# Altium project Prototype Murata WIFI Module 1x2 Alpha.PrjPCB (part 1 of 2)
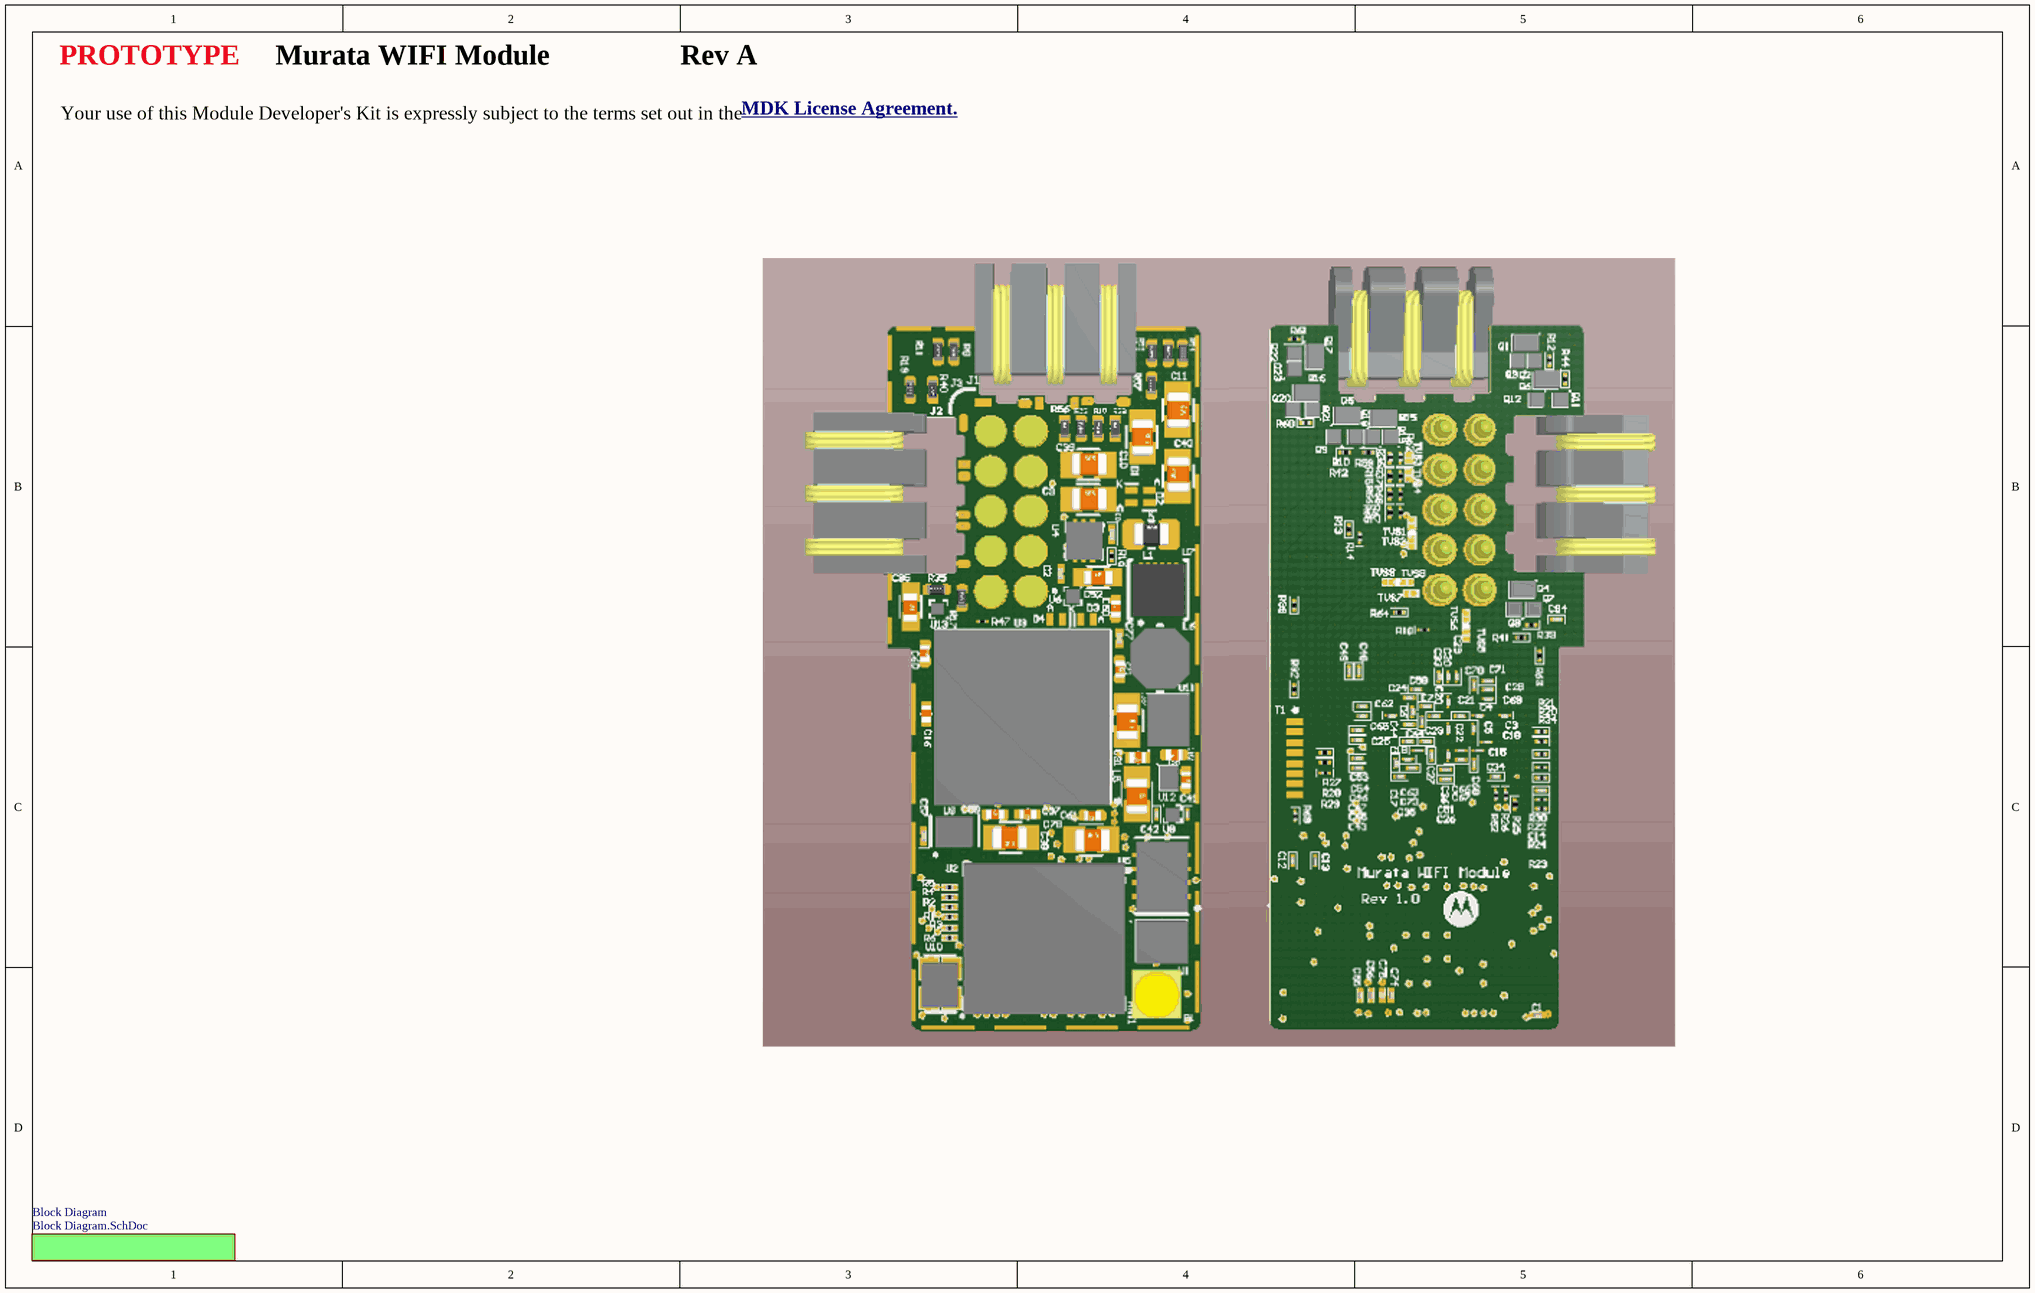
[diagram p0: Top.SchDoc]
revision: A
11 sheets, 196 parts. Net scope: flat (ports and power ports of the same name join across sheets).
Board file: Prototype Murata WIFI Module 1x2 Alpha.PcbDoc
Sheets:
  Top.SchDoc
    Block Diagram = Block Diagram.SchDoc
      EPM = EPM.SchDoc
      Host Comm = Host Comm.SchDoc
      FPGA = FPGA.SchDoc
        Banks = FPGA Banks.SchDoc
        SERDES = FPGA Serdes.SchDoc
        Power = FPGA Power.SchDoc
        Configuration = FPGA Config.SchDoc
      ARA_1X2_Power = Power.SchDoc
      WIFI Module = WIFI Module.SchDoc

## Sheet Top.SchDoc: Top (License)
size B; Date: 3/12/2014; Engineer: David McCoy (Cospan Design); DocumentNumber: 1; Revision: A; SheetNumber: 1; SheetTotal: 11

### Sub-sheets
Block Diagram = Block Diagram.SchDoc: no entries

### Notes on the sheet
- PROTOTYPE
- Murata WIFI Module
- Rev A
- Your use of this Module Developer's Kit is expressly subject to the terms set out in the
- MDK License Agreement. <http://www.projectara.com/mdk-license.txt>

## Sheet Block Diagram.SchDoc: Block Diagram
size B; Date: 10/29/2013; DrawnBy: David McCoy; Engineer: David McCoy (Cospan Design); DocumentNumber: 2; Revision: A; SheetNumber: 2; SheetTotal: 11
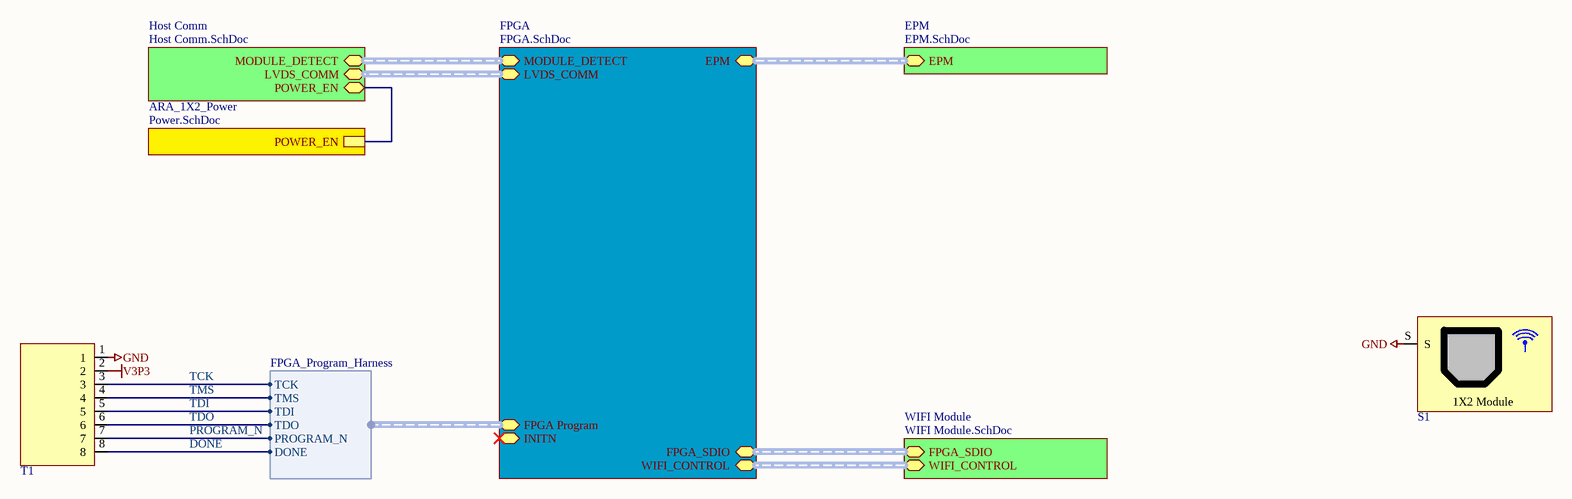
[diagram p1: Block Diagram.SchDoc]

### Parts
S1  RFSHIELD  [RFSHIELD_1X2_MODULE]  (value not drawn)  (no BOM)
T1  8 PIN TEST_INTERFACE  [8-PIN Test Interface]  (value not drawn)  (no BOM)

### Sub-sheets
ARA_1X2_Power = Power.SchDoc: POWER_EN
EPM = EPM.SchDoc: EPM (harness EPM_Harness)
FPGA = FPGA.SchDoc: EPM (harness EPM_Harness), FPGA Program (harness FPGA_Program_Harness), INITN, MODULE_DETECT (harness Module_Detect_Harness), LVDS_COMM (harness LVDS_Comm_Harness), FPGA_SDIO (harness SDIO Harness), WIFI_CONTROL (harness WIFI Control Harness)
Host Comm = Host Comm.SchDoc: MODULE_DETECT (harness Module_Detect_Harness), LVDS_COMM (harness LVDS_Comm_Harness), POWER_EN
WIFI Module = WIFI Module.SchDoc: FPGA_SDIO (harness SDIO Harness), WIFI_CONTROL (harness WIFI Control Harness)

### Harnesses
FPGA_Program_Harness: TCK, TMS, TDI, TDO, PROGRAM_N, DONE

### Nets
GND: S1.S T1.1
V3P3: T1.2
DONE: T1.8 ; sheet FPGA/FPGA Program.DONE
PROGRAM_N: T1.7 ; sheet FPGA/FPGA Program.PROGRAM_N
TCK: T1.3 ; sheet FPGA/FPGA Program.TCK
TDI: T1.5 ; sheet FPGA/FPGA Program.TDI
TDO: T1.6 ; sheet FPGA/FPGA Program.TDO
TMS: T1.4 ; sheet FPGA/FPGA Program.TMS
(unnamed): sheet Host Comm/POWER_EN, sheet ARA_1X2_Power/POWER_EN

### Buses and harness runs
harness sheet EPM/EPM = sheet FPGA/EPM
harness sheet FPGA/FPGA_SDIO = sheet WIFI Module/FPGA_SDIO
harness sheet FPGA/LVDS_COMM = sheet Host Comm/LVDS_COMM
harness sheet FPGA/MODULE_DETECT = sheet Host Comm/MODULE_DETECT
harness sheet FPGA/WIFI_CONTROL = sheet WIFI Module/WIFI_CONTROL

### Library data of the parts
S1 = S_RF_SHIELD_1X2_MODULE
T1 = TEST_INTERFACE: 8 PIN Test Interface

## Sheet EPM.SchDoc: EPM
size C; Date: 10/29/2013; DrawnBy: David McCoy; Engineer: David McCoy (Cospan Design); DocumentNumber: 10; Revision: A; SheetNumber: 10; SheetTotal: 11
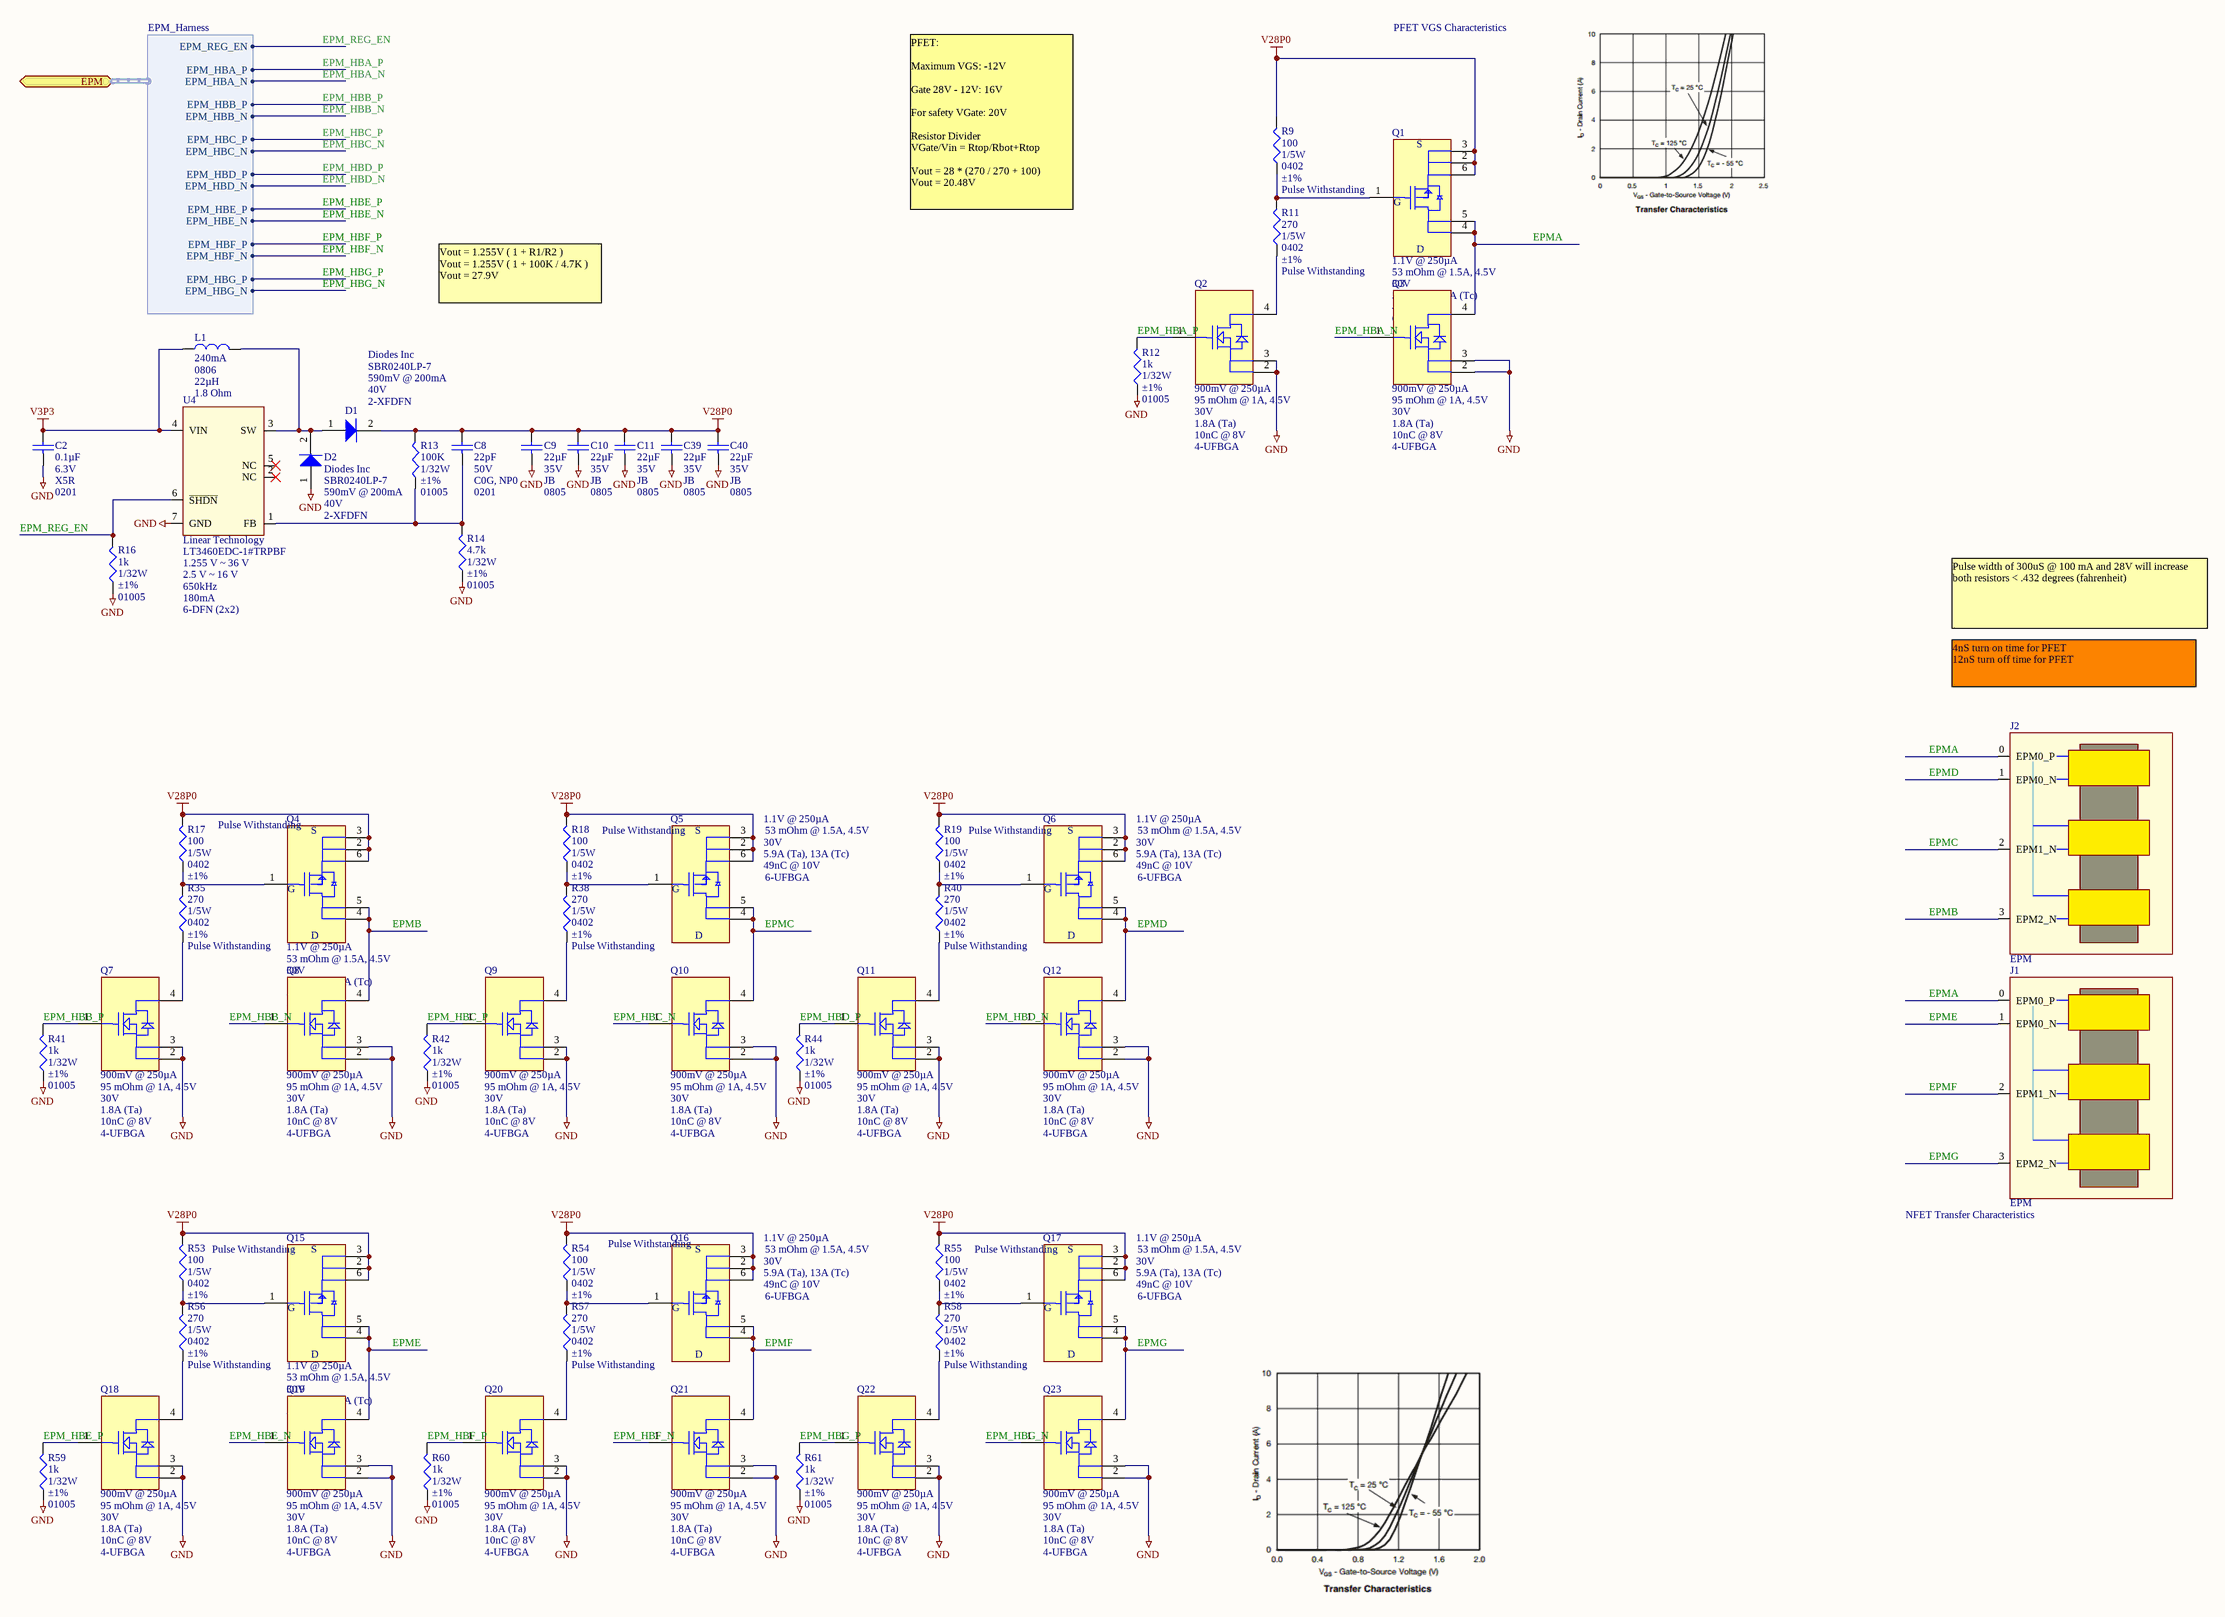
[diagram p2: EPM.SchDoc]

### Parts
C2  Capacitance: 0.1µF  Voltage - Rated: 6.3V  Temperature Coefficient: X5R  Package / Case: 0201  [CAPC0201]  (hidden comment: 0.1UF)
C8  Capacitance: 22pF  Voltage - Rated: 50V  Temperature Coefficient: C0G, NP0  Package / Case: 0201  [CAPC0201]  (hidden comment: C_0201_22pF)
C9  Voltage - Rated: 35V  Temperature Coefficient: JB  Package / Case: 0805  [C_ERA-0805]  (hidden comment: 22µF)
C10  Voltage - Rated: 35V  Temperature Coefficient: JB  Package / Case: 0805  [C_ERA-0805]  (hidden comment: 22µF)
C11  Voltage - Rated: 35V  Temperature Coefficient: JB  Package / Case: 0805  [C_ERA-0805]  (hidden comment: 22µF)
C39  Voltage - Rated: 35V  Temperature Coefficient: JB  Package / Case: 0805  [C_ERA-0805]  (hidden comment: 22µF)
C40  Voltage - Rated: 35V  Temperature Coefficient: JB  Package / Case: 0805  [C_ERA-0805]  (hidden comment: 22µF)
D1  Manufacturer: Diodes Inc  Voltage - Forward (Vf) (Max) @ If: 590mV @ 200mA  Voltage - DC Reverse (Vr) (Max): 40V  [2-XFDFN]  (hidden comment: SBR0240LP-7)
D2  Manufacturer: Diodes Inc  Voltage - Forward (Vf) (Max) @ If: 590mV @ 200mA  Voltage - DC Reverse (Vr) (Max): 40V  [2-XFDFN]  (hidden comment: SBR0240LP-7)
J1  EPM  [EPM_3X_CON_BO]  (no BOM)
J2  EPM  [EPM_3X_CON_FRANK]  (no BOM)
L1  Current: 240mA  Package / Case: 0806  Inductance: 22µH  DC Resistance (DCR): 1.8 Ohm  [L_0806]  (hidden comment: CBC2016T220K)
Q1  Vgs(th) (Max) @ Id: 1.1V @ 250µA  Rds On (Max) @ Id, Vgs: 53 mOhm @ 1.5A, 4.5V  Drain to Source Voltage (Vdss): 30V  Current - Continuous Drain (Id) @ 25° C: 5.9A (Ta), 13A (Tc)  Gate Charge (Qg) @ Vgs: 49nC @ 10V  Supplier Device Package: 6-UFBGA  [BGA6C50P3X2_145X96X59]  (hidden comment: SI8497DB-T2-E1)
Q2  Vgs(th) (Max) @ Id: 900mV @ 250µA  Rds On (Max) @ Id, Vgs: 95 mOhm @ 1A, 4.5V  Drain to Source Voltage (Vdss): 30V  Current - Continuous Drain (Id) @ 25° C: 1.8A (Ta)  Gate Charge (Qg) @ Vgs: 10nC @ 8V  Supplier Device Package: 4-UFBGA  [BGA4C40P2X2_80X80X40]  (hidden comment: SI8808DB-T2-E1)
Q3  Vgs(th) (Max) @ Id: 900mV @ 250µA  Rds On (Max) @ Id, Vgs: 95 mOhm @ 1A, 4.5V  Drain to Source Voltage (Vdss): 30V  Current - Continuous Drain (Id) @ 25° C: 1.8A (Ta)  Gate Charge (Qg) @ Vgs: 10nC @ 8V  Supplier Device Package: 4-UFBGA  [BGA4C40P2X2_80X80X40]  (hidden comment: SI8808DB-T2-E1)
Q4  Vgs(th) (Max) @ Id: 1.1V @ 250µA  Rds On (Max) @ Id, Vgs: 53 mOhm @ 1.5A, 4.5V  Drain to Source Voltage (Vdss): 30V  Current - Continuous Drain (Id) @ 25° C: 5.9A (Ta), 13A (Tc)  Gate Charge (Qg) @ Vgs: 49nC @ 10V  Supplier Device Package: 6-UFBGA  [BGA6C50P3X2_145X96X59]  (hidden comment: SI8497DB-T2-E1)
Q5  Vgs(th) (Max) @ Id: 1.1V @ 250µA  Rds On (Max) @ Id, Vgs: 53 mOhm @ 1.5A, 4.5V  Drain to Source Voltage (Vdss): 30V  Current - Continuous Drain (Id) @ 25° C: 5.9A (Ta), 13A (Tc)  Gate Charge (Qg) @ Vgs: 49nC @ 10V  Supplier Device Package: 6-UFBGA  [BGA6C50P3X2_145X96X59]  (hidden comment: SI8497DB-T2-E1)
Q6  Vgs(th) (Max) @ Id: 1.1V @ 250µA  Rds On (Max) @ Id, Vgs: 53 mOhm @ 1.5A, 4.5V  Drain to Source Voltage (Vdss): 30V  Current - Continuous Drain (Id) @ 25° C: 5.9A (Ta), 13A (Tc)  Gate Charge (Qg) @ Vgs: 49nC @ 10V  Supplier Device Package: 6-UFBGA  [BGA6C50P3X2_145X96X59]  (hidden comment: SI8497DB-T2-E1)
Q7  Vgs(th) (Max) @ Id: 900mV @ 250µA  Rds On (Max) @ Id, Vgs: 95 mOhm @ 1A, 4.5V  Drain to Source Voltage (Vdss): 30V  Current - Continuous Drain (Id) @ 25° C: 1.8A (Ta)  Gate Charge (Qg) @ Vgs: 10nC @ 8V  Supplier Device Package: 4-UFBGA  [BGA4C40P2X2_80X80X40]  (hidden comment: SI8808DB-T2-E1)
Q8  Vgs(th) (Max) @ Id: 900mV @ 250µA  Rds On (Max) @ Id, Vgs: 95 mOhm @ 1A, 4.5V  Drain to Source Voltage (Vdss): 30V  Current - Continuous Drain (Id) @ 25° C: 1.8A (Ta)  Gate Charge (Qg) @ Vgs: 10nC @ 8V  Supplier Device Package: 4-UFBGA  [BGA4C40P2X2_80X80X40]  (hidden comment: SI8808DB-T2-E1)
Q9  Vgs(th) (Max) @ Id: 900mV @ 250µA  Rds On (Max) @ Id, Vgs: 95 mOhm @ 1A, 4.5V  Drain to Source Voltage (Vdss): 30V  Current - Continuous Drain (Id) @ 25° C: 1.8A (Ta)  Gate Charge (Qg) @ Vgs: 10nC @ 8V  Supplier Device Package: 4-UFBGA  [BGA4C40P2X2_80X80X40]  (hidden comment: SI8808DB-T2-E1)
Q10  Vgs(th) (Max) @ Id: 900mV @ 250µA  Rds On (Max) @ Id, Vgs: 95 mOhm @ 1A, 4.5V  Drain to Source Voltage (Vdss): 30V  Current - Continuous Drain (Id) @ 25° C: 1.8A (Ta)  Gate Charge (Qg) @ Vgs: 10nC @ 8V  Supplier Device Package: 4-UFBGA  [BGA4C40P2X2_80X80X40]  (hidden comment: SI8808DB-T2-E1)
Q11  Vgs(th) (Max) @ Id: 900mV @ 250µA  Rds On (Max) @ Id, Vgs: 95 mOhm @ 1A, 4.5V  Drain to Source Voltage (Vdss): 30V  Current - Continuous Drain (Id) @ 25° C: 1.8A (Ta)  Gate Charge (Qg) @ Vgs: 10nC @ 8V  Supplier Device Package: 4-UFBGA  [BGA4C40P2X2_80X80X40]  (hidden comment: SI8808DB-T2-E1)
Q12  Vgs(th) (Max) @ Id: 900mV @ 250µA  Rds On (Max) @ Id, Vgs: 95 mOhm @ 1A, 4.5V  Drain to Source Voltage (Vdss): 30V  Current - Continuous Drain (Id) @ 25° C: 1.8A (Ta)  Gate Charge (Qg) @ Vgs: 10nC @ 8V  Supplier Device Package: 4-UFBGA  [BGA4C40P2X2_80X80X40]  (hidden comment: SI8808DB-T2-E1)
Q15  Vgs(th) (Max) @ Id: 1.1V @ 250µA  Rds On (Max) @ Id, Vgs: 53 mOhm @ 1.5A, 4.5V  Drain to Source Voltage (Vdss): 30V  Current - Continuous Drain (Id) @ 25° C: 5.9A (Ta), 13A (Tc)  Gate Charge (Qg) @ Vgs: 49nC @ 10V  Supplier Device Package: 6-UFBGA  [BGA6C50P3X2_145X96X59]  (hidden comment: SI8497DB-T2-E1)
Q16  Vgs(th) (Max) @ Id: 1.1V @ 250µA  Rds On (Max) @ Id, Vgs: 53 mOhm @ 1.5A, 4.5V  Drain to Source Voltage (Vdss): 30V  Current - Continuous Drain (Id) @ 25° C: 5.9A (Ta), 13A (Tc)  Gate Charge (Qg) @ Vgs: 49nC @ 10V  Supplier Device Package: 6-UFBGA  [BGA6C50P3X2_145X96X59]  (hidden comment: SI8497DB-T2-E1)
Q17  Vgs(th) (Max) @ Id: 1.1V @ 250µA  Rds On (Max) @ Id, Vgs: 53 mOhm @ 1.5A, 4.5V  Drain to Source Voltage (Vdss): 30V  Current - Continuous Drain (Id) @ 25° C: 5.9A (Ta), 13A (Tc)  Gate Charge (Qg) @ Vgs: 49nC @ 10V  Supplier Device Package: 6-UFBGA  [BGA6C50P3X2_145X96X59]  (hidden comment: SI8497DB-T2-E1)
Q18  Vgs(th) (Max) @ Id: 900mV @ 250µA  Rds On (Max) @ Id, Vgs: 95 mOhm @ 1A, 4.5V  Drain to Source Voltage (Vdss): 30V  Current - Continuous Drain (Id) @ 25° C: 1.8A (Ta)  Gate Charge (Qg) @ Vgs: 10nC @ 8V  Supplier Device Package: 4-UFBGA  [BGA4C40P2X2_80X80X40]  (hidden comment: SI8808DB-T2-E1)
Q19  Vgs(th) (Max) @ Id: 900mV @ 250µA  Rds On (Max) @ Id, Vgs: 95 mOhm @ 1A, 4.5V  Drain to Source Voltage (Vdss): 30V  Current - Continuous Drain (Id) @ 25° C: 1.8A (Ta)  Gate Charge (Qg) @ Vgs: 10nC @ 8V  Supplier Device Package: 4-UFBGA  [BGA4C40P2X2_80X80X40]  (hidden comment: SI8808DB-T2-E1)
Q20  Vgs(th) (Max) @ Id: 900mV @ 250µA  Rds On (Max) @ Id, Vgs: 95 mOhm @ 1A, 4.5V  Drain to Source Voltage (Vdss): 30V  Current - Continuous Drain (Id) @ 25° C: 1.8A (Ta)  Gate Charge (Qg) @ Vgs: 10nC @ 8V  Supplier Device Package: 4-UFBGA  [BGA4C40P2X2_80X80X40]  (hidden comment: SI8808DB-T2-E1)
Q21  Vgs(th) (Max) @ Id: 900mV @ 250µA  Rds On (Max) @ Id, Vgs: 95 mOhm @ 1A, 4.5V  Drain to Source Voltage (Vdss): 30V  Current - Continuous Drain (Id) @ 25° C: 1.8A (Ta)  Gate Charge (Qg) @ Vgs: 10nC @ 8V  Supplier Device Package: 4-UFBGA  [BGA4C40P2X2_80X80X40]  (hidden comment: SI8808DB-T2-E1)
Q22  Vgs(th) (Max) @ Id: 900mV @ 250µA  Rds On (Max) @ Id, Vgs: 95 mOhm @ 1A, 4.5V  Drain to Source Voltage (Vdss): 30V  Current - Continuous Drain (Id) @ 25° C: 1.8A (Ta)  Gate Charge (Qg) @ Vgs: 10nC @ 8V  Supplier Device Package: 4-UFBGA  [BGA4C40P2X2_80X80X40]  (hidden comment: SI8808DB-T2-E1)
Q23  Vgs(th) (Max) @ Id: 900mV @ 250µA  Rds On (Max) @ Id, Vgs: 95 mOhm @ 1A, 4.5V  Drain to Source Voltage (Vdss): 30V  Current - Continuous Drain (Id) @ 25° C: 1.8A (Ta)  Gate Charge (Qg) @ Vgs: 10nC @ 8V  Supplier Device Package: 4-UFBGA  [BGA4C40P2X2_80X80X40]  (hidden comment: SI8808DB-T2-E1)
R9  Power (Watts): 1/5W  Case: 0402  Tolerance: ±1%  [R_0402]  (hidden comment: 100)
R11  Power (Watts): 1/5W  Case: 0402  Tolerance: ±1%  [R_0402]  (hidden comment: 270)
R12  Power (Watts): 1/32W  Tolerance: ±1%  Case: 01005  [R_01005]  (hidden comment: 1k)
R13  Resistance In Ohms: 100K  Power (Watts): 1/32W  Tolerance: ±1%  Case: 01005  [R_01005]  (hidden comment: 10K)
R14  Power (Watts): 1/32W  Tolerance: ±1%  Case: 01005  [R_01005]  (hidden comment: 4.7k)
R16  Power (Watts): 1/32W  Tolerance: ±1%  Case: 01005  [R_01005]  (hidden comment: 1k)
R17  Power (Watts): 1/5W  Case: 0402  Tolerance: ±1%  [R_0402]  (hidden comment: 100)
R18  Power (Watts): 1/5W  Case: 0402  Tolerance: ±1%  [R_0402]  (hidden comment: 100)
R19  Power (Watts): 1/5W  Case: 0402  Tolerance: ±1%  [R_0402]  (hidden comment: 100)
R35  Power (Watts): 1/5W  Case: 0402  Tolerance: ±1%  [R_0402]  (hidden comment: 270)
R38  Power (Watts): 1/5W  Case: 0402  Tolerance: ±1%  [R_0402]  (hidden comment: 270)
R40  Power (Watts): 1/5W  Case: 0402  Tolerance: ±1%  [R_0402]  (hidden comment: 270)
R41  Power (Watts): 1/32W  Tolerance: ±1%  Case: 01005  [R_01005]  (hidden comment: 1k)
R42  Power (Watts): 1/32W  Tolerance: ±1%  Case: 01005  [R_01005]  (hidden comment: 1k)
R44  Power (Watts): 1/32W  Tolerance: ±1%  Case: 01005  [R_01005]  (hidden comment: 1k)
R53  Power (Watts): 1/5W  Case: 0402  Tolerance: ±1%  [R_0402]  (hidden comment: 100)
R54  Power (Watts): 1/5W  Case: 0402  Tolerance: ±1%  [R_0402]  (hidden comment: 100)
R55  Power (Watts): 1/5W  Case: 0402  Tolerance: ±1%  [R_0402]  (hidden comment: 100)
R56  Power (Watts): 1/5W  Case: 0402  Tolerance: ±1%  [R_0402]  (hidden comment: 270)
R57  Power (Watts): 1/5W  Case: 0402  Tolerance: ±1%  [R_0402]  (hidden comment: 270)
R58  Power (Watts): 1/5W  Case: 0402  Tolerance: ±1%  [R_0402]  (hidden comment: 270)
R59  Power (Watts): 1/32W  Tolerance: ±1%  Case: 01005  [R_01005]  (hidden comment: 1k)
R60  Power (Watts): 1/32W  Tolerance: ±1%  Case: 01005  [R_01005]  (hidden comment: 1k)
R61  Power (Watts): 1/32W  Tolerance: ±1%  Case: 01005  [R_01005]  (hidden comment: 1k)
U4  Manufacturer: Linear Technology  Manufacturer Part Number: LT3460EDC-1#TRPBF  Voltage - Output: 1.255 V ~ 36 V  Voltage - Input: 2.5 V ~ 16 V  Frequency - Switching: 650kHz  Current - Output: 180mA  Supplier Device Package: 6-DFN (2x2)  [DFN6]  (hidden comment: U_LT3460EDC-1)

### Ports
EPM (harness EPM_Harness)

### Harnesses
EPM_Harness: EPM_REG_EN, EPM_HBA_P, EPM_HBA_N, EPM_HBB_P, EPM_HBB_N, EPM_HBC_P, EPM_HBC_N, EPM_HBD_P, EPM_HBD_N, EPM_HBE_P, EPM_HBE_N, EPM_HBF_P, EPM_HBF_N, EPM_HBG_P, EPM_HBG_N

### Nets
GND: C2.1 C9.1 C10.1 C11.1 C39.1 C40.1 D2.1(A) Q2.2(S2) Q2.3(S) Q3.2(S2) Q3.3(S) Q7.2(S2) Q7.3(S) Q8.2(S2) Q8.3(S) Q9.2(S2) Q9.3(S) Q10.2(S2) Q10.3(S) Q11.2(S2) Q11.3(S) Q12.2(S2) Q12.3(S) Q18.2(S2) Q18.3(S) Q19.2(S2) Q19.3(S) Q20.2(S2) Q20.3(S) Q21.2(S2) Q21.3(S) Q22.2(S2) Q22.3(S) Q23.2(S2) Q23.3(S) R12.2 R14.2 R16.2 R41.2 R42.2 R44.2 R59.2 R60.2 R61.2 U4.7(GND)
V3P3: C2.2 L1.1 U4.4(VIN)
V28P0: C8.2 C9.2 C10.2 C11.2 C39.2 C40.2 D1.2(K) Q1.2(S2) Q1.3(S) Q1.6(S3) Q4.2(S2) Q4.3(S) Q4.6(S3) Q5.2(S2) Q5.3(S) Q5.6(S3) Q6.2(S2) Q6.3(S) Q6.6(S3) Q15.2(S2) Q15.3(S) Q15.6(S3) Q16.2(S2) Q16.3(S) Q16.6(S3) Q17.2(S2) Q17.3(S) Q17.6(S3) R9.1 R13.1 R17.1 R18.1 R19.1 R53.1 R54.1 R55.1
EPM_HBA_N: Q3.1(G) ; port EPM.EPM_HBA_N
EPM_HBA_P: Q2.1(G) R12.1 ; port EPM.EPM_HBA_P
EPM_HBB_N: Q8.1(G) ; port EPM.EPM_HBB_N
EPM_HBB_P: Q7.1(G) R41.1 ; port EPM.EPM_HBB_P
EPM_HBC_N: Q10.1(G) ; port EPM.EPM_HBC_N
EPM_HBC_P: Q9.1(G) R42.1 ; port EPM.EPM_HBC_P
EPM_HBD_N: Q12.1(G) ; port EPM.EPM_HBD_N
EPM_HBD_P: Q11.1(G) R44.1 ; port EPM.EPM_HBD_P
EPM_HBE_N: Q19.1(G) ; port EPM.EPM_HBE_N
EPM_HBE_P: Q18.1(G) R59.1 ; port EPM.EPM_HBE_P
EPM_HBF_N: Q21.1(G) ; port EPM.EPM_HBF_N
EPM_HBF_P: Q20.1(G) R60.1 ; port EPM.EPM_HBF_P
EPM_HBG_N: Q23.1(G) ; port EPM.EPM_HBG_N
EPM_HBG_P: Q22.1(G) R61.1 ; port EPM.EPM_HBG_P
EPM_REG_EN: R16.1 U4.6(~{SHDN}) ; port EPM.EPM_REG_EN
EPMA: J1.0(EPM0_P) J2.0(EPM0_P) Q1.4(D1) Q1.5(D2) Q3.4(D)
EPMB: J2.3(EPM2_N) Q4.4(D1) Q4.5(D2) Q8.4(D)
EPMC: J2.2(EPM1_N) Q5.4(D1) Q5.5(D2) Q10.4(D)
EPMD: J2.1(EPM0_N) Q6.4(D1) Q6.5(D2) Q12.4(D)
EPME: J1.1(EPM0_N) Q15.4(D1) Q15.5(D2) Q19.4(D)
EPMF: J1.2(EPM1_N) Q16.4(D1) Q16.5(D2) Q21.4(D)
EPMG: J1.3(EPM2_N) Q17.4(D1) Q17.5(D2) Q23.4(D)
NetC8_1: C8.1 R13.2 R14.1 U4.1(FB)
NetD1_1: D1.1(A) D2.2(K) L1.2 U4.3(SW)
NetQ1_1: Q1.1(G) R9.2 R11.1
NetQ2_4: Q2.4(D) R11.2
NetQ4_1: Q4.1(G) R17.2 R35.1
NetQ5_1: Q5.1(G) R18.2 R38.1
NetQ6_1: Q6.1(G) R19.2 R40.1
NetQ7_4: Q7.4(D) R35.2
NetQ9_4: Q9.4(D) R38.2
NetQ11_4: Q11.4(D) R40.2
NetQ15_1: Q15.1(G) R53.2 R56.1
NetQ16_1: Q16.1(G) R54.2 R57.1
NetQ17_1: Q17.1(G) R55.2 R58.1
NetQ18_4: Q18.4(D) R56.2
NetQ20_4: Q20.4(D) R57.2
NetQ22_4: Q22.4(D) R58.2

Not connected (* = marked no-connect by the designer): U4 2(NC)* 5(NC)*

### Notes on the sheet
- PFET VGS Characteristics
- PFET:
  Maximum VGS: -12V
  Gate 28V - 12V: 16V
  For safety VGate: 20V
  Resistor Divider
  VGate/Vin = Rtop/Rbot+Rtop
  Vout = 28 * (270 / 270 + 100)
  Vout = 20.48V
- Vout = 1.255V ( 1 + R1/R2 )
  Vout = 1.255V ( 1 + 100K / 4.7K )
  Vout = 27.9V
- Pulse width of 300uS @ 100 mA and 28V will increase both resistors < .432 degrees (fahrenheit)
- 4nS turn on time for PFET
  12nS turn off time for PFET
- NFET Transfer Characteristics

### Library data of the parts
C2 = C_0201_0.1UF: CAP CER 0.1UF 6.3V 10% X5R 0201; Manufacturer: TDK Corporation; Manufacturer Part Number: C0603X5R0J104M; Tolerance: ±20%
C8 = C_0201_22pF: CAP CER 22PF 50V 5% NP0 0201; Manufacturer: TDK Corporation; Manufacturer Part Number: C0603C0G1H220J030BA
C9-C11 C39 C40 = C_0805_22µF_35V: CAP CER 22UF 35V 20% JB 0805; Manufacturer: TDK Corporation; Manufacturer Part Number: C2012JB1V226M125AC
D1 D2 = D_SBR0240LP-7: DIODE SUP BARRIER 40V 0.25A 2DFN; Diode Type: Super Barrier; Current - Average Rectified (Io): 250mA; Speed: Fast Recovery =< 500ns, > 200mA (Io); Current - Reverse Leakage @ Vr: 10µA @ 40V; Thermal Resistance: 270°C/W Ja
J1 = J_EPM_3_PAD_BO
J2 = J_EPM_3_PAD_FRANK
L1 = L_0806_22uH: INDUCTOR 22UH 10% 0806 SMD; Manufacturer: Taiyo Yuden; Type: Wirewound; Current - Saturation: 250mA; Shielding: Unshielded; Frequency - Self Resonant: 16MHz; Frequency - Test: 2.52MHz
Q1 Q4-Q6 Q15-Q17 = Q_PFET_BGA_30V: MOSFET P-CH D-S 30V MICROFOOT; Manufacturer: Vishay Siliconix; FET Type: MOSFET P-Channel, Metal Oxide; FET Feature: Logic Level Gate, 2.5V Drive; Input Capacitance (Ciss) @ Vds: 1320pF @ 15V; Power - Max: 13W
Q2 Q3 Q7-Q12 Q18-Q23 = Q_NFET_BGA_30V: MOSFET N-CH D-S 30V MICROFOOT; Manufacturer: Vishay Siliconix; FET Type: MOSFET N-Channel, Metal Oxide; FET Feature: Logic Level Gate, 1.5V Drive; Input Capacitance (Ciss) @ Vds: 330pF @ 15V
R9 R17-R19 R53-R55 = R_0402_100_5%_PW: RES 100 OHM 1/5W 5% 0402 SMD; Manufacturer: Rohm Semiconductor; Manufacturer Part Number: ESR01MZPJ101; Temperature Coefficient: ±200ppm/°C
R11 R35 R38 R40 R56-R58 = R_0402_270_5%_PW: RES 270 OHM 1/5W 5% 0402 SMD; Manufacturer: Rohm Semiconductor; Manufacturer Part Number: ESR01MZPJ271; Temperature Coefficient: ±200ppm/°C
R12 R16 R41 R42 R44 R59-R61 = R_01005_1k: RES 1K OHM 1/32W 1% 01005 SM; Manufacturer: Panasonic Electronic Components; Manufacturer Part Number: ERJ-XGNF1001Y; Temperature Coefficient: ±200ppm/°C
R13 = R_01005_100K: RES 100K OHM 1/32W 1% 01005 SMD; Manufacturer: Yageo; Manufacturer Part Number: RC0100FR-07100KL; Temperature Coefficient: ±250ppm/°C
R14 = R_01005_4.7k: RES 4.7K OHM 1/32W 1% 01005 SMD; Manufacturer: Yageo; Manufacturer Part Number: RC0100FR-074K7L; Temperature Coefficient: ±250ppm/°C
U4 = U_LTC3460-1: IC REG BOOST ADJ 0.18A 6DFN; Output Type: Adjustable; Number of Outputs: 1; PWM Type: Current Mode; Synchronous Rectifier: No

## Sheet Host Comm.SchDoc: Host Comm
size B; Date: 10/29/2013; DrawnBy: David McCoy; Engineer: David McCoy (Cospan Design); DocumentNumber: 9; Revision: A; SheetNumber: 9; SheetTotal: 11
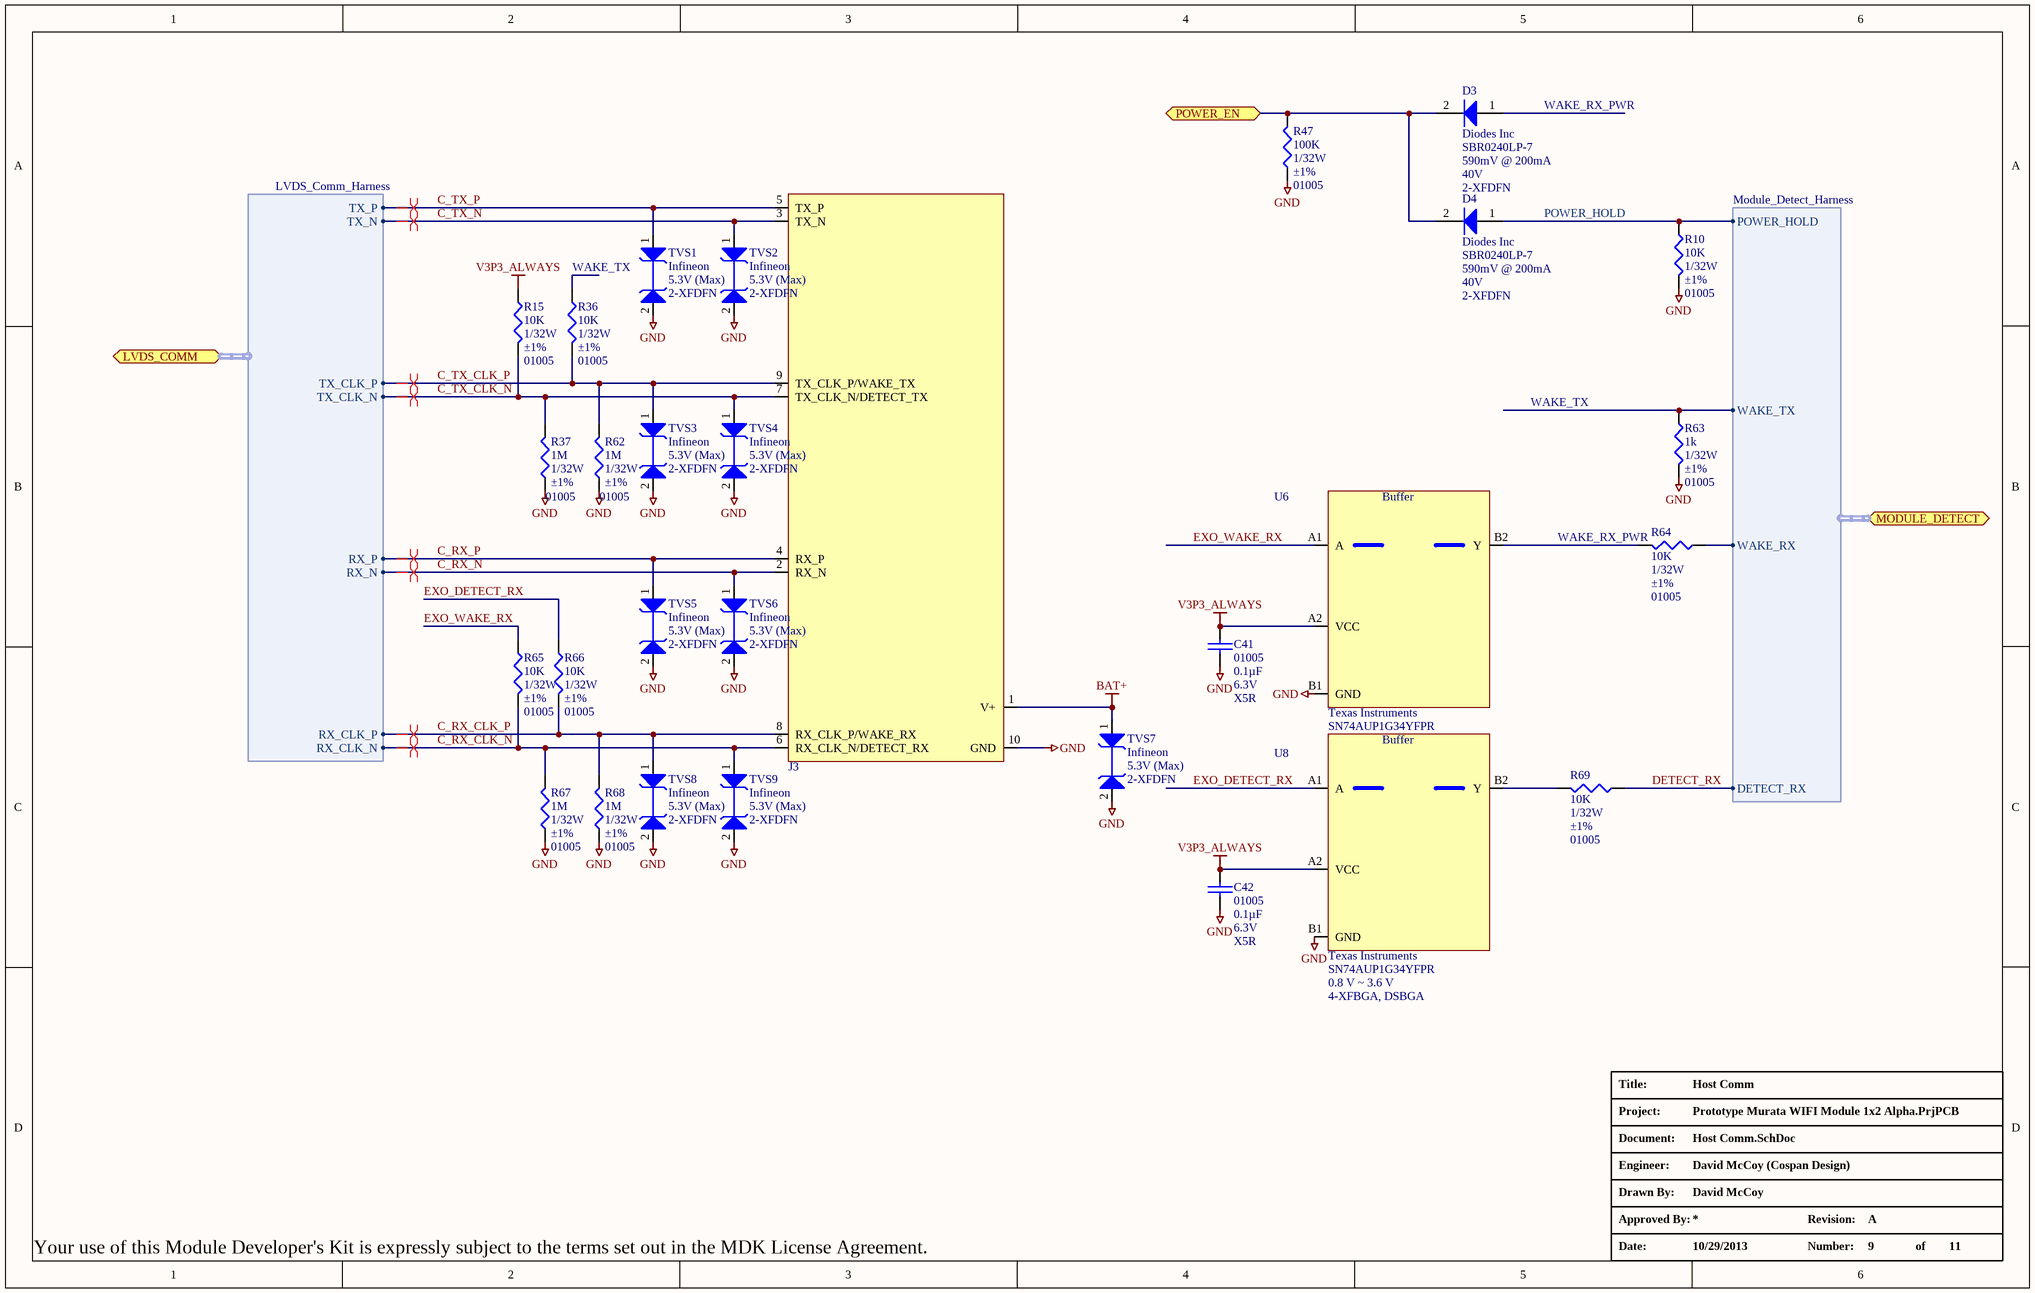
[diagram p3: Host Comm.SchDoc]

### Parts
C41  Package / Case: 01005  Capacitance: 0.1µF  Voltage - Rated: 6.3V  Temperature Coefficient: X5R  [C_01005]  (hidden comment: 0.1uF)
C42  Package / Case: 01005  Capacitance: 0.1µF  Voltage - Rated: 6.3V  Temperature Coefficient: X5R  [C_01005]  (hidden comment: 0.1uF)
D3  Manufacturer: Diodes Inc  Voltage - Forward (Vf) (Max) @ If: 590mV @ 200mA  Voltage - DC Reverse (Vr) (Max): 40V  [2-XFDFN]  (hidden comment: SBR0240LP-7)
D4  Manufacturer: Diodes Inc  Voltage - Forward (Vf) (Max) @ If: 590mV @ 200mA  Voltage - DC Reverse (Vr) (Max): 40V  [2-XFDFN]  (hidden comment: SBR0240LP-7)
J3  SPRING PIN  [10PIN SMD CONNECTOR]  (value not drawn)  (no BOM)
R10  Power (Watts): 1/32W  Tolerance: ±1%  Case: 01005  [R_01005]  (hidden comment: 10K)
R15  Power (Watts): 1/32W  Tolerance: ±1%  Case: 01005  [R_01005]  (hidden comment: 10K)
R36  Power (Watts): 1/32W  Tolerance: ±1%  Case: 01005  [R_01005]  (hidden comment: 10K)
R37  Resistance In Ohms: 1M  Power (Watts): 1/32W  Tolerance: ±1%  Case: 01005  [R_01005]  (hidden comment: 1M Ohms)
R47  Power (Watts): 1/32W  Tolerance: ±1%  Case: 01005  [R_01005]  (hidden comment: 100K)
R62  Resistance In Ohms: 1M  Power (Watts): 1/32W  Tolerance: ±1%  Case: 01005  [R_01005]  (hidden comment: 1M Ohms)
R63  Power (Watts): 1/32W  Tolerance: ±1%  Case: 01005  [R_01005]  (hidden comment: 1k)
R64  Power (Watts): 1/32W  Tolerance: ±1%  Case: 01005  [R_01005]  (hidden comment: 10K)
R65  Power (Watts): 1/32W  Tolerance: ±1%  Case: 01005  [R_01005]  (hidden comment: 10K)
R66  Power (Watts): 1/32W  Tolerance: ±1%  Case: 01005  [R_01005]  (hidden comment: 10K)
R67  Resistance In Ohms: 1M  Power (Watts): 1/32W  Tolerance: ±1%  Case: 01005  [R_01005]  (hidden comment: 1M Ohms)
R68  Resistance In Ohms: 1M  Power (Watts): 1/32W  Tolerance: ±1%  Case: 01005  [R_01005]  (hidden comment: 1M Ohms)
R69  Power (Watts): 1/32W  Tolerance: ±1%  Case: 01005  [R_01005]  (hidden comment: 10K)
TVS1  Manufacturer: Infineon  Voltage - Reverse Standoff (Typ): 5.3V (Max)  Package / Case: 2-XFDFN  [TSSLP-2-1]  (hidden comment: TVS_HS_ESD)
TVS2  Manufacturer: Infineon  Voltage - Reverse Standoff (Typ): 5.3V (Max)  Package / Case: 2-XFDFN  [TSSLP-2-1]  (hidden comment: TVS_HS_ESD)
TVS3  Manufacturer: Infineon  Voltage - Reverse Standoff (Typ): 5.3V (Max)  Package / Case: 2-XFDFN  [TSSLP-2-1]  (hidden comment: TVS_HS_ESD)
TVS4  Manufacturer: Infineon  Voltage - Reverse Standoff (Typ): 5.3V (Max)  Package / Case: 2-XFDFN  [TSSLP-2-1]  (hidden comment: TVS_HS_ESD)
TVS5  Manufacturer: Infineon  Voltage - Reverse Standoff (Typ): 5.3V (Max)  Package / Case: 2-XFDFN  [TSSLP-2-1]  (hidden comment: TVS_HS_ESD)
TVS6  Manufacturer: Infineon  Voltage - Reverse Standoff (Typ): 5.3V (Max)  Package / Case: 2-XFDFN  [TSSLP-2-1]  (hidden comment: TVS_HS_ESD)
TVS7  Manufacturer: Infineon  Voltage - Reverse Standoff (Typ): 5.3V (Max)  Package / Case: 2-XFDFN  [TSSLP-2-1]  (hidden comment: TVS_HS_ESD)
TVS8  Manufacturer: Infineon  Voltage - Reverse Standoff (Typ): 5.3V (Max)  Package / Case: 2-XFDFN  [TSSLP-2-1]  (hidden comment: TVS_HS_ESD)
TVS9  Manufacturer: Infineon  Voltage - Reverse Standoff (Typ): 5.3V (Max)  Package / Case: 2-XFDFN  [TSSLP-2-1]  (hidden comment: TVS_HS_ESD)
U6  Manufacturer: Texas Instruments  Manufacturer Part Number: SN74AUP1G34YFPR  Voltage - Supply: 0.8 V ~ 3.6 V  Package / Case: 4-XFBGA, DSBGA  [DSBGA4_.4MM]  (hidden comment: Buffer)
U8  Manufacturer: Texas Instruments  Manufacturer Part Number: SN74AUP1G34YFPR  Voltage - Supply: 0.8 V ~ 3.6 V  Package / Case: 4-XFBGA, DSBGA  [DSBGA4_.4MM]  (hidden comment: Buffer)

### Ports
LVDS_COMM (harness LVDS_Comm_Harness), MODULE_DETECT (harness Module_Detect_Harness), POWER_EN

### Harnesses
Module_Detect_Harness: WAKE_TX, WAKE_RX, DETECT_RX, POWER_HOLD
LVDS_Comm_Harness: TX_P, TX_N, TX_CLK_P, TX_CLK_N, RX_P, RX_N, RX_CLK_P, RX_CLK_N

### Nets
BAT+: J3.1(V+) TVS7.1
GND: C41.1 C42.1 J3.10(GND) R10.1 R37.2 R47.2 R62.2 R63.1 R67.2 R68.2 TVS1.2 TVS2.2 TVS3.2 TVS4.2 TVS5.2 TVS6.2 TVS7.2 TVS8.2 TVS9.2 U6.B1(GND) U8.B1(GND)
V3P3_ALWAYS: C41.2 C42.2 R15.2 U6.A2(VCC) U8.A2(VCC)
C_RX_CLK_N: J3.6(RX_CLK_N/DETECT_RX) R65.1 R67.1 TVS9.1 ; port LVDS_COMM.RX_CLK_N
C_RX_CLK_P: J3.8(RX_CLK_P/WAKE_RX) R66.1 R68.1 TVS8.1 ; port LVDS_COMM.RX_CLK_P
C_RX_N: J3.2(RX_N) TVS6.1 ; port LVDS_COMM.RX_N
C_RX_P: J3.4(RX_P) TVS5.1 ; port LVDS_COMM.RX_P
C_TX_CLK_N: J3.7(TX_CLK_N/DETECT_TX) R15.1 R37.1 TVS4.1 ; port LVDS_COMM.TX_CLK_N
C_TX_CLK_P: J3.9(TX_CLK_P/WAKE_TX) R36.1 R62.1 TVS3.1 ; port LVDS_COMM.TX_CLK_P
C_TX_N: J3.3(TX_N) TVS2.1 ; port LVDS_COMM.TX_N
C_TX_P: J3.5(TX_P) TVS1.1 ; port LVDS_COMM.TX_P
DETECT_RX: R69.2 ; port MODULE_DETECT.DETECT_RX
EXO_DETECT_RX: R66.2 U8.A1(A)
EXO_WAKE_RX: R65.2 U6.A1(A)
POWER_EN: D3.2(K) D4.2(K) R47.1 ; port POWER_EN
POWER_HOLD: D4.1(A) R10.2 ; port MODULE_DETECT.POWER_HOLD
WAKE_RX: R64.2 ; port MODULE_DETECT.WAKE_RX
WAKE_RX_PWR: D3.1(A) R64.1 U6.B2(Y)
WAKE_TX: R36.2 R63.2 ; port MODULE_DETECT.WAKE_TX
NetR69_1: R69.1 U8.B2(Y)

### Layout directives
differential pair: C_RX_CLK_N, C_RX_CLK_P, C_RX_N, C_RX_P, C_TX_CLK_N, C_TX_CLK_P, C_TX_N, C_TX_P

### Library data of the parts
C41 C42 = C_01005_0.1uF: CAP CER 0.1UF 6.3V 20% X5R 01005; Manufacturer: TDK Corporation; Manufacturer Part Number: C0402X5R0J104M020BC
D3 D4 = D_SBR0240LP-7: as D1 on sheet EPM
J3 = J_TONKA_MODULE_CONNECTOR
R10 R15 R36 R64-R66 R69 = R_01005_10K: RES 10K OHM 1/32W 1% 01005; Manufacturer: Samsung Electro-Mechanics America, Inc; Manufacturer Part Number: RC0402F103CS; Temperature Coefficient: ±250ppm/°C
R37 R62 R67 R68 = R_01005_1M: RES 1M OHM 1/32W 1% 01005 SMD; Manufacturer: Yageo; Manufacturer Part Number: RC0100FR-071ML; Temperature Coefficient: ±250ppm/°C
R47 = R_01005_100K: as R13 on sheet EPM
R63 = R_01005_1k: as R12 on sheet EPM
TVS1-TVS9 = TVS_HS_ESD: TVS DIODE 5.3VWM 28VC TSSLP2-1; Manufacturer Part Number: ESD5V3U1U-02LS E6327; Unidirectional Channels: 1; Voltage - Breakdown (Min): 6V; Voltage - Clamping (Max) @ Ipp: 28V (Typ); Current - Peak Pulse (10/1000µs): 3A (8/20µs); Power Line Protection: No; Capacitance @ Frequency: 0.4pF @ 1MHz
U6 U8 = U_SN74AUP1G34YFPR: IC BUFFER GATE SGL 4-DSBGA; Logic Type: Buffer/Line Driver, Non-Inverting; Number of Elements: 1; Current - Output High, Low: 4mA, 4mA

## Sheet FPGA.SchDoc: FPGA
size B; Date: 10/29/2013; DrawnBy: David McCoy; Engineer: David McCoy (Cospan Design); DocumentNumber: 3; Revision: A; SheetNumber: 3; SheetTotal: 11
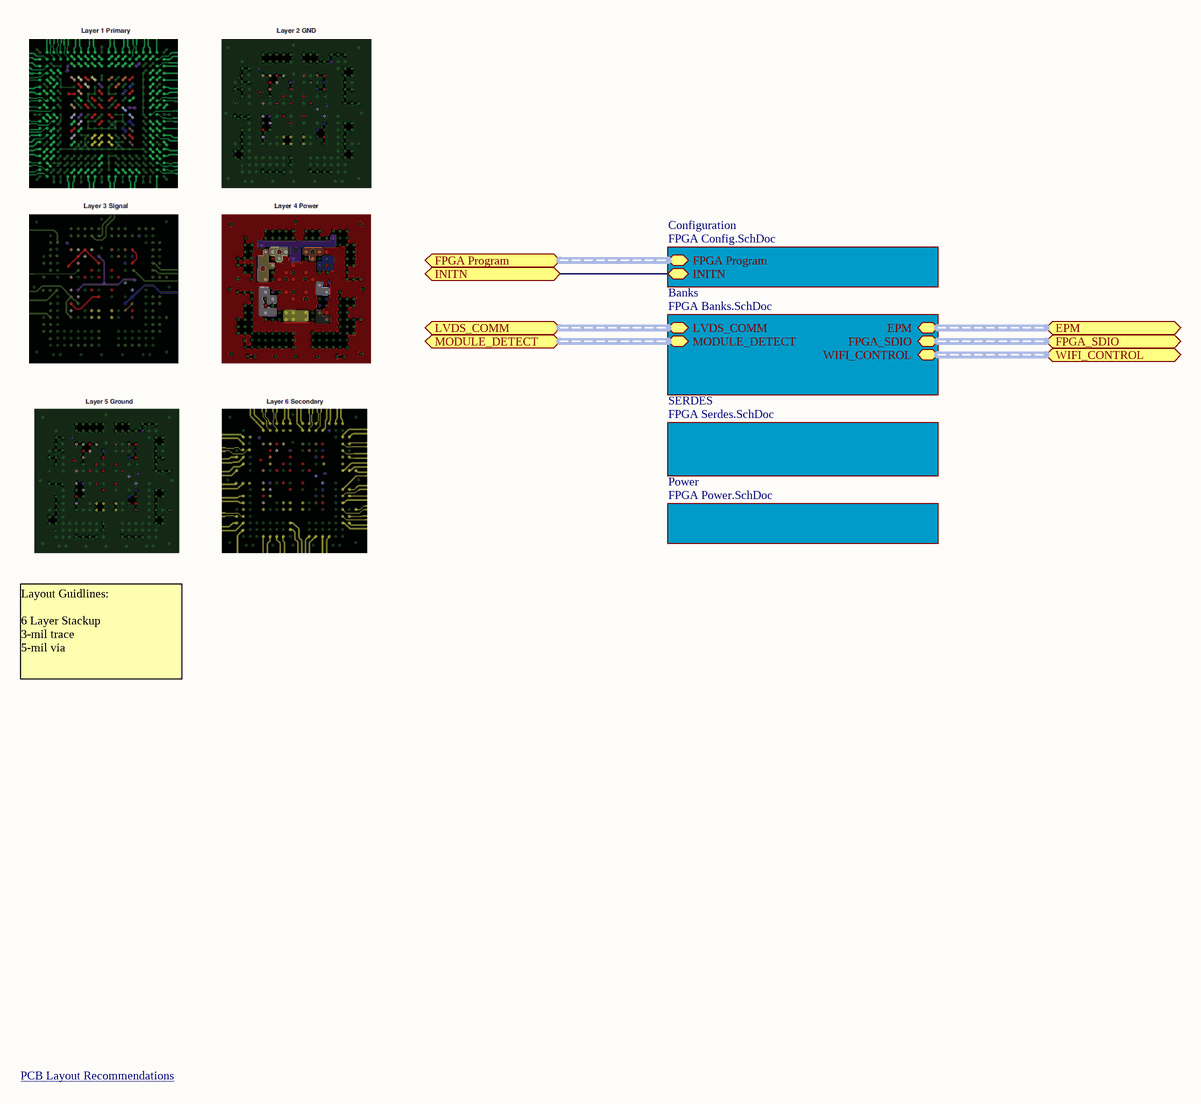
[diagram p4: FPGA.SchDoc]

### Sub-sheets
Banks = FPGA Banks.SchDoc: EPM (harness EPM_Harness), MODULE_DETECT (harness Module_Detect_Harness), LVDS_COMM (harness LVDS_Comm_Harness), FPGA_SDIO (harness SDIO Harness), WIFI_CONTROL (harness WIFI Control Harness)
Configuration = FPGA Config.SchDoc: FPGA Program (harness FPGA_Program_Harness), INITN
Power = FPGA Power.SchDoc: no entries
SERDES = FPGA Serdes.SchDoc: no entries

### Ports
EPM (harness EPM_Harness), FPGA Program (harness FPGA_Program_Harness), FPGA_SDIO (harness SDIO Harness), INITN, LVDS_COMM (harness LVDS_Comm_Harness), MODULE_DETECT (harness Module_Detect_Harness), WIFI_CONTROL (harness WIFI Control Harness)

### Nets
INITN: port INITN, sheet Configuration/INITN

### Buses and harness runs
harness port EPM = sheet Banks/EPM
harness port FPGA Program = sheet Configuration/FPGA Program
harness port FPGA_SDIO = sheet Banks/FPGA_SDIO
harness port LVDS_COMM = sheet Banks/LVDS_COMM
harness port MODULE_DETECT = sheet Banks/MODULE_DETECT
harness port WIFI_CONTROL = sheet Banks/WIFI_CONTROL

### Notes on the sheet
- Layout Guidlines:
  6 Layer Stackup
  3-mil trace
  5-mil via
- PCB Layout Recommendations <http://www.latticesemi.com/~/media/Documents/ApplicationNotes/PCBLayoutRecommendationsforBGAPackages.pdf?document_id=671>

## Sheet FPGA Banks.SchDoc: FPGA Banks
size B; Date: 10/29/2013; DrawnBy: David McCoy; Engineer: David McCoy (Cospan Design); DocumentNumber: 5; Revision: A; SheetNumber: 5; SheetTotal: 11
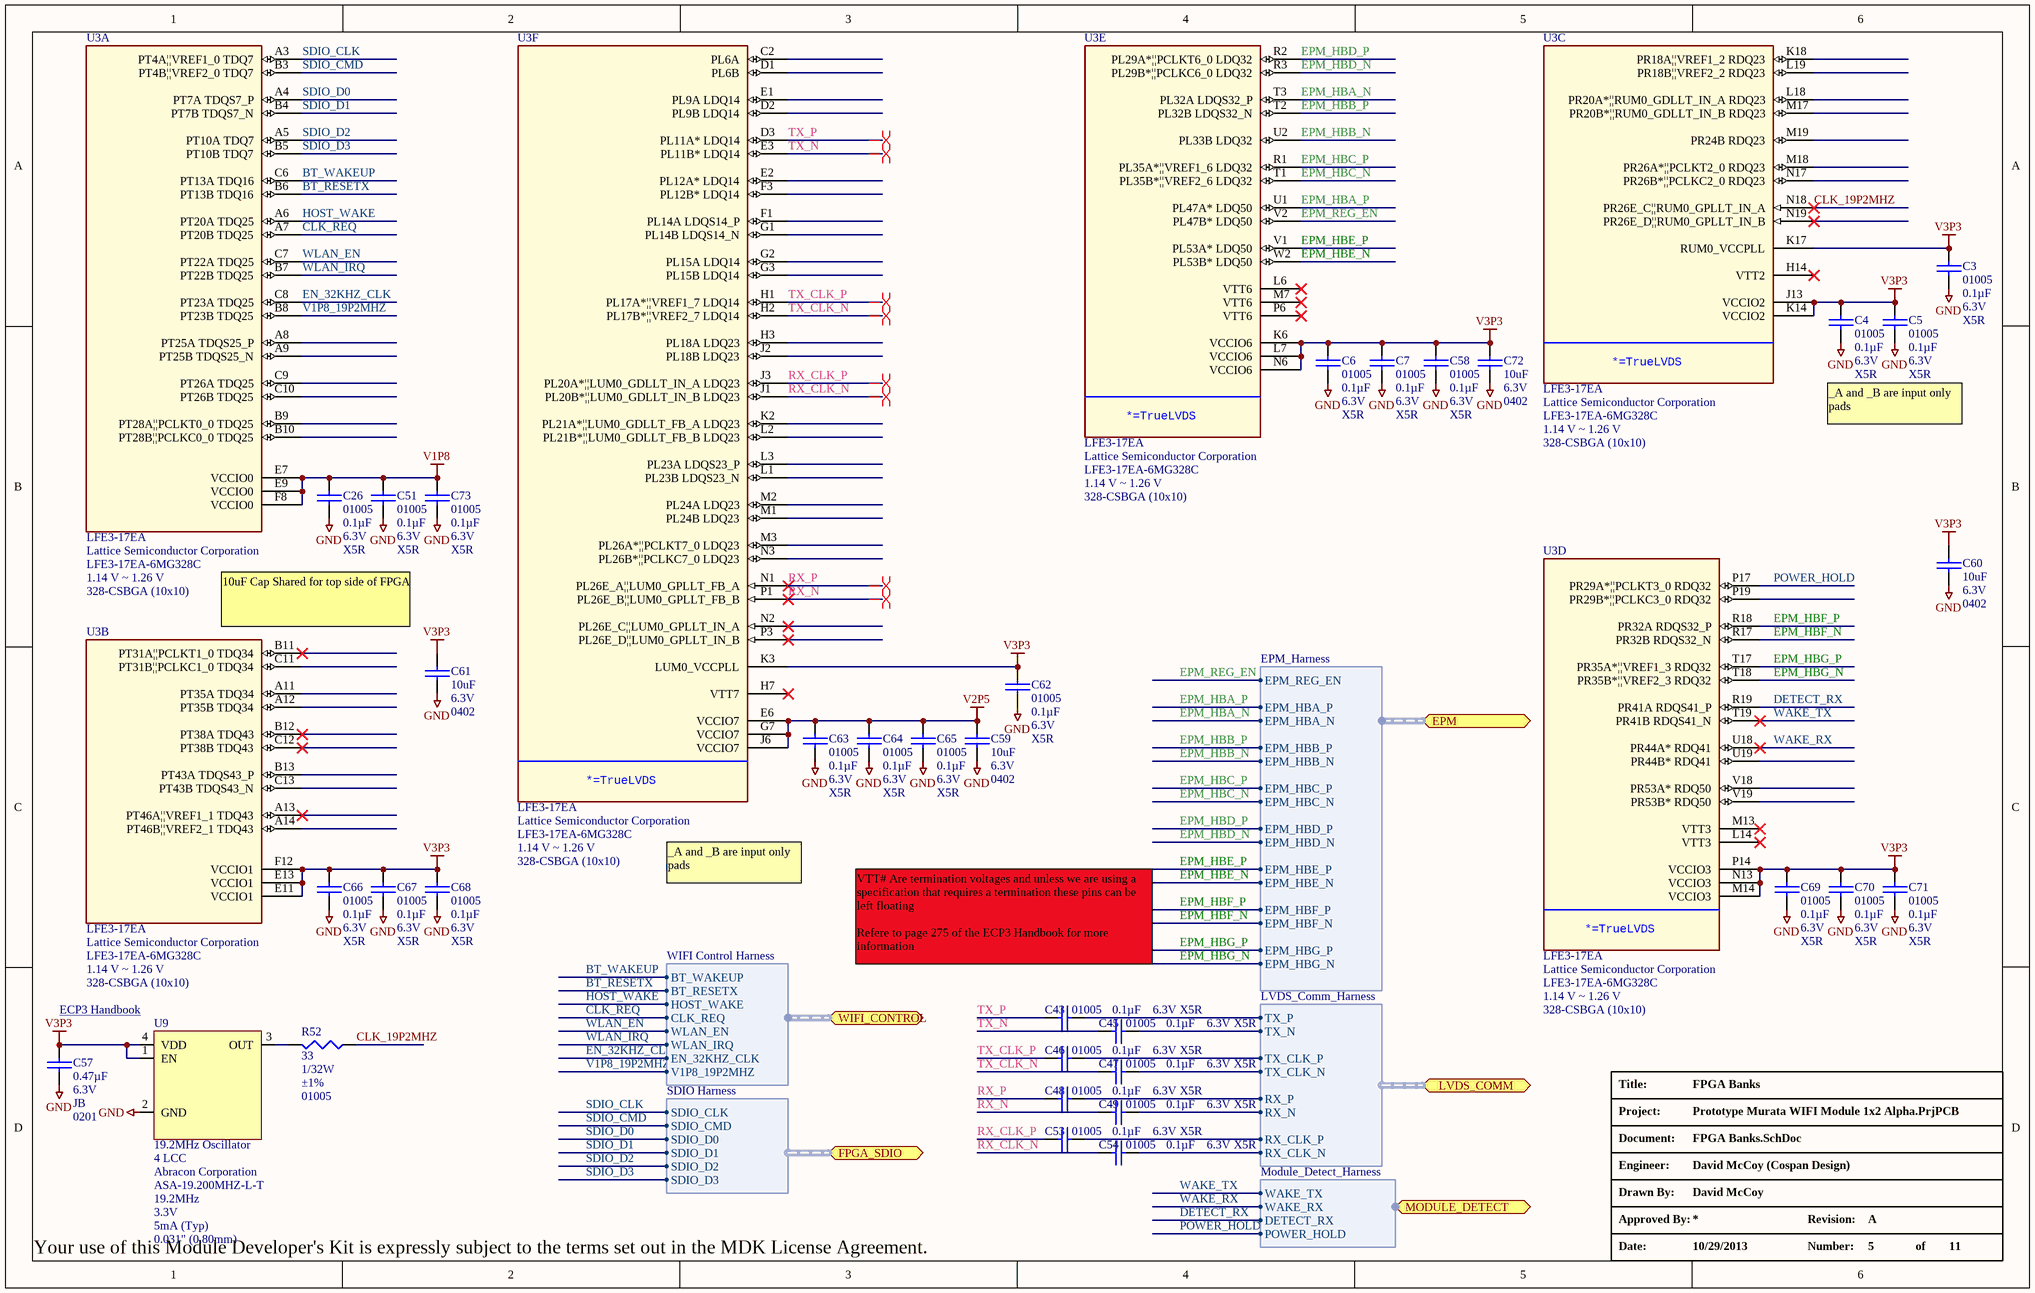
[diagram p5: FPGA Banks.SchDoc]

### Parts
C3  Package / Case: 01005  Capacitance: 0.1µF  Voltage - Rated: 6.3V  Temperature Coefficient: X5R  [C_01005]  (hidden comment: 0.1uF)
C4  Package / Case: 01005  Capacitance: 0.1µF  Voltage - Rated: 6.3V  Temperature Coefficient: X5R  [C_01005]  (hidden comment: 0.1uF)
C5  Package / Case: 01005  Capacitance: 0.1µF  Voltage - Rated: 6.3V  Temperature Coefficient: X5R  [C_01005]  (hidden comment: 0.1uF)
C6  Package / Case: 01005  Capacitance: 0.1µF  Voltage - Rated: 6.3V  Temperature Coefficient: X5R  [C_01005]  (hidden comment: 0.1uF)
C7  Package / Case: 01005  Capacitance: 0.1µF  Voltage - Rated: 6.3V  Temperature Coefficient: X5R  [C_01005]  (hidden comment: 0.1uF)
C26  Package / Case: 01005  Capacitance: 0.1µF  Voltage - Rated: 6.3V  Temperature Coefficient: X5R  [C_01005]  (hidden comment: 0.1uF)
C43  Package / Case: 01005  Capacitance: 0.1µF  Voltage - Rated: 6.3V  Temperature Coefficient: X5R  [C_01005]  (hidden comment: 0.1uF)
C45  Package / Case: 01005  Capacitance: 0.1µF  Voltage - Rated: 6.3V  Temperature Coefficient: X5R  [C_01005]  (hidden comment: 0.1uF)
C46  Package / Case: 01005  Capacitance: 0.1µF  Voltage - Rated: 6.3V  Temperature Coefficient: X5R  [C_01005]  (hidden comment: 0.1uF)
C47  Package / Case: 01005  Capacitance: 0.1µF  Voltage - Rated: 6.3V  Temperature Coefficient: X5R  [C_01005]  (hidden comment: 0.1uF)
C48  Package / Case: 01005  Capacitance: 0.1µF  Voltage - Rated: 6.3V  Temperature Coefficient: X5R  [C_01005]  (hidden comment: 0.1uF)
C49  Package / Case: 01005  Capacitance: 0.1µF  Voltage - Rated: 6.3V  Temperature Coefficient: X5R  [C_01005]  (hidden comment: 0.1uF)
C51  Package / Case: 01005  Capacitance: 0.1µF  Voltage - Rated: 6.3V  Temperature Coefficient: X5R  [C_01005]  (hidden comment: 0.1uF)
C53  Package / Case: 01005  Capacitance: 0.1µF  Voltage - Rated: 6.3V  Temperature Coefficient: X5R  [C_01005]  (hidden comment: 0.1uF)
C54  Package / Case: 01005  Capacitance: 0.1µF  Voltage - Rated: 6.3V  Temperature Coefficient: X5R  [C_01005]  (hidden comment: 0.1uF)
C57  Voltage - Rated: 6.3V  Temperature Coefficient: JB  Package / Case: 0201  [CAPC0201]  (hidden comment: 0.47µF)
C58  Package / Case: 01005  Capacitance: 0.1µF  Voltage - Rated: 6.3V  Temperature Coefficient: X5R  [C_01005]  (hidden comment: 0.1uF)
C59  Voltage - Rated: 6.3V  Package / Case: 0402  [C_0402]  (hidden comment: 10uF)
C60  Voltage - Rated: 6.3V  Package / Case: 0402  [C_0402]  (hidden comment: 10uF)
C61  Voltage - Rated: 6.3V  Package / Case: 0402  [C_0402]  (hidden comment: 10uF)
C62  Package / Case: 01005  Capacitance: 0.1µF  Voltage - Rated: 6.3V  Temperature Coefficient: X5R  [C_01005]  (hidden comment: 0.1uF)
C63  Package / Case: 01005  Capacitance: 0.1µF  Voltage - Rated: 6.3V  Temperature Coefficient: X5R  [C_01005]  (hidden comment: 0.1uF)
C64  Package / Case: 01005  Capacitance: 0.1µF  Voltage - Rated: 6.3V  Temperature Coefficient: X5R  [C_01005]  (hidden comment: 0.1uF)
C65  Package / Case: 01005  Capacitance: 0.1µF  Voltage - Rated: 6.3V  Temperature Coefficient: X5R  [C_01005]  (hidden comment: 0.1uF)
C66  Package / Case: 01005  Capacitance: 0.1µF  Voltage - Rated: 6.3V  Temperature Coefficient: X5R  [C_01005]  (hidden comment: 0.1uF)
C67  Package / Case: 01005  Capacitance: 0.1µF  Voltage - Rated: 6.3V  Temperature Coefficient: X5R  [C_01005]  (hidden comment: 0.1uF)
C68  Package / Case: 01005  Capacitance: 0.1µF  Voltage - Rated: 6.3V  Temperature Coefficient: X5R  [C_01005]  (hidden comment: 0.1uF)
C69  Package / Case: 01005  Capacitance: 0.1µF  Voltage - Rated: 6.3V  Temperature Coefficient: X5R  [C_01005]  (hidden comment: 0.1uF)
C70  Package / Case: 01005  Capacitance: 0.1µF  Voltage - Rated: 6.3V  Temperature Coefficient: X5R  [C_01005]  (hidden comment: 0.1uF)
C71  Package / Case: 01005  Capacitance: 0.1µF  Voltage - Rated: 6.3V  Temperature Coefficient: X5R  [C_01005]  (hidden comment: 0.1uF)
C72  Voltage - Rated: 6.3V  Package / Case: 0402  [C_0402]  (hidden comment: 10uF)
C73  Package / Case: 01005  Capacitance: 0.1µF  Voltage - Rated: 6.3V  Temperature Coefficient: X5R  [C_01005]  (hidden comment: 0.1uF)
R52  Power (Watts): 1/32W  Tolerance: ±1%  Case: 01005  [R_01005]  (hidden comment: 33)
U3  LFE3-17EA  Manufacturer: Lattice Semiconductor Corporation  Manufacturer Part Number: LFE3-17EA-6MG328C  Voltage - Supply: 1.14 V ~ 1.26 V  Supplier Device Package: 328-CSBGA (10x10)  [BGA328C50P19X19_1000X1000X150]  (parts A,B,C,D,E,F of 10)
U9  19.2MHz Oscillator  Package / Case: 4 LCC  Manufacturer: Abracon Corporation  Manufacturer Part Number: ASA-19.200MHZ-L-T  Frequency: 19.2MHz  Voltage - Supply: 3.3V  Current - Supply (Max): 5mA (Typ)  Height: 0.031" (0.80mm)  [LCCS165P160X200X70-4N]

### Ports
EPM (harness EPM_Harness), FPGA_SDIO (harness SDIO Harness), LVDS_COMM (harness LVDS_Comm_Harness), MODULE_DETECT (harness Module_Detect_Harness), WIFI_CONTROL (harness WIFI Control Harness)

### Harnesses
EPM_Harness: EPM_REG_EN, EPM_HBA_P, EPM_HBA_N, EPM_HBB_P, EPM_HBB_N, EPM_HBC_P, EPM_HBC_N, EPM_HBD_P, EPM_HBD_N, EPM_HBE_P, EPM_HBE_N, EPM_HBF_P, EPM_HBF_N, EPM_HBG_P, EPM_HBG_N
LVDS_Comm_Harness: TX_P, TX_N, TX_CLK_P, TX_CLK_N, RX_P, RX_N, RX_CLK_P, RX_CLK_N
Module_Detect_Harness: WAKE_TX, WAKE_RX, DETECT_RX, POWER_HOLD
SDIO Harness: SDIO_CLK, SDIO_CMD, SDIO_D0, SDIO_D1, SDIO_D2, SDIO_D3
WIFI Control Harness: BT_WAKEUP, BT_RESETX, HOST_WAKE, CLK_REQ, WLAN_EN, WLAN_IRQ, EN_32KHZ_CLK, V1P8_19P2MHZ

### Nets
GND: C3.1 C4.1 C5.1 C6.1 C7.1 C26.1 C51.1 C57.1 C58.1 C59.1 C60.1 C61.1 C62.1 C63.1 C64.1 C65.1 C66.1 C67.1 C68.1 C69.1 C70.1 C71.1 C72.1 C73.1 U9.2(GND)
V1P8: C26.2 C51.2 C73.2 U3.E7(VCCIO0) U3.E9(VCCIO0) U3.F8(VCCIO0)
V2P5: C59.2 C63.2 C64.2 C65.2 U3.E6(VCCIO7) U3.G7(VCCIO7) U3.J6(VCCIO7)
V3P3: C3.2 C4.2 C5.2 C6.2 C7.2 C57.2 C58.2 C60.2 C61.2 C62.2 C66.2 C67.2 C68.2 C69.2 C70.2 C71.2 C72.2 U3.E11(VCCIO1) U3.E13(VCCIO1) U3.F12(VCCIO1) U3.J13(VCCIO2) U3.K3(LUM0_VCCPLL) U3.K6(VCCIO6) U3.K14(VCCIO2) U3.K17(RUM0_VCCPLL) U3.L7(VCCIO6) U3.M14(VCCIO3) U3.N6(VCCIO6) U3.N13(VCCIO3) U3.P14(VCCIO3) U9.1(EN) U9.4(VDD)
BT_RESETX: U3.B6(PT13B_TDQ16) ; port WIFI_CONTROL.BT_RESETX
BT_WAKEUP: U3.C6(PT13A_TDQ16) ; port WIFI_CONTROL.BT_WAKEUP
C_RX_CLK_N: C54.1 ; port LVDS_COMM.RX_CLK_N
C_RX_CLK_P: C53.1 ; port LVDS_COMM.RX_CLK_P
C_RX_N: C49.1 ; port LVDS_COMM.RX_N
C_RX_P: C48.1 ; port LVDS_COMM.RX_P
C_TX_CLK_N: C47.1 ; port LVDS_COMM.TX_CLK_N
C_TX_CLK_P: C46.1 ; port LVDS_COMM.TX_CLK_P
C_TX_N: C45.1 ; port LVDS_COMM.TX_N
C_TX_P: C43.1 ; port LVDS_COMM.TX_P
CLK_19P2MHZ: R52.2 U3.N18(PR26E_C¦¦RUM0_GPLLT_IN_A)
CLK_REQ: U3.A7(PT20B_TDQ25) ; port WIFI_CONTROL.CLK_REQ
DETECT_RX: U3.R19(PR41A_RDQS41_P) ; port MODULE_DETECT.DETECT_RX
EN_32KHZ_CLK: U3.C8(PT23A_TDQ25) ; port WIFI_CONTROL.EN_32KHZ_CLK
EPM_HBA_N: U3.T3(PL32A_LDQS32_P) ; port EPM.EPM_HBA_N
EPM_HBA_P: U3.U1(PL47A*_LDQ50) ; port EPM.EPM_HBA_P
EPM_HBB_N: U3.U2(PL33B_LDQ32) ; port EPM.EPM_HBB_N
EPM_HBB_P: U3.T2(PL32B_LDQS32_N) ; port EPM.EPM_HBB_P
EPM_HBC_N: U3.T1(PL35B*¦¦VREF2_6_LDQ32) ; port EPM.EPM_HBC_N
EPM_HBC_P: U3.R1(PL35A*¦¦VREF1_6_LDQ32) ; port EPM.EPM_HBC_P
EPM_HBD_N: U3.R3(PL29B*¦¦PCLKC6_0_LDQ32) ; port EPM.EPM_HBD_N
EPM_HBD_P: U3.R2(PL29A*¦¦PCLKT6_0_LDQ32) ; port EPM.EPM_HBD_P
EPM_HBE_N: U3.W2(PL53B*_LDQ50) ; port EPM.EPM_HBE_N
EPM_HBE_P: U3.V1(PL53A*_LDQ50) ; port EPM.EPM_HBE_P
EPM_HBF_N: U3.R17(PR32B_RDQS32_N) ; port EPM.EPM_HBF_N
EPM_HBF_P: U3.R18(PR32A_RDQS32_P) ; port EPM.EPM_HBF_P
EPM_HBG_N: U3.T18(PR35B*¦¦VREF2_3_RDQ32) ; port EPM.EPM_HBG_N
EPM_HBG_P: U3.T17(PR35A*¦¦VREF1_3_RDQ32) ; port EPM.EPM_HBG_P
EPM_REG_EN: U3.V2(PL47B*_LDQ50) ; port EPM.EPM_REG_EN
HOST_WAKE: U3.A6(PT20A_TDQ25) ; port WIFI_CONTROL.HOST_WAKE
POWER_HOLD: U3.P17(PR29A*¦¦PCLKT3_0_RDQ32) ; port MODULE_DETECT.POWER_HOLD
RX_CLK_N: C54.2 U3.J1(PL20B*¦¦LUM0_GDLLT_IN_B_LDQ23)
RX_CLK_P: C53.2 U3.J3(PL20A*¦¦LUM0_GDLLT_IN_A_LDQ23)
RX_N: C49.2 U3.P1(PL26E_B¦¦LUM0_GPLLT_FB_B)
RX_P: C48.2 U3.N1(PL26E_A¦¦LUM0_GPLLT_FB_A)
SDIO_CLK: U3.A3(PT4A¦¦VREF1_0_TDQ7) ; port FPGA_SDIO.SDIO_CLK
SDIO_CMD: U3.B3(PT4B¦¦VREF2_0_TDQ7) ; port FPGA_SDIO.SDIO_CMD
SDIO_D0: U3.A4(PT7A_TDQS7_P) ; port FPGA_SDIO.SDIO_D0
SDIO_D1: U3.B4(PT7B_TDQS7_N) ; port FPGA_SDIO.SDIO_D1
SDIO_D2: U3.A5(PT10A_TDQ7) ; port FPGA_SDIO.SDIO_D2
SDIO_D3: U3.B5(PT10B_TDQ7) ; port FPGA_SDIO.SDIO_D3
TX_CLK_N: C47.2 U3.H2(PL17B*¦¦VREF2_7_LDQ14)
TX_CLK_P: C46.2 U3.H1(PL17A*¦¦VREF1_7_LDQ14)
TX_N: C45.2 U3.E3(PL11B*_LDQ14)
TX_P: C43.2 U3.D3(PL11A*_LDQ14)
V1P8_19P2MHZ: U3.B8(PT23B_TDQ25) ; port WIFI_CONTROL.V1P8_19P2MHZ
WAKE_RX: U3.U18(PR44A*_RDQ41) ; port MODULE_DETECT.WAKE_RX
WAKE_TX: U3.T19(PR41B_RDQS41_N) ; port MODULE_DETECT.WAKE_TX
WLAN_EN: U3.C7(PT22A_TDQ25) ; port WIFI_CONTROL.WLAN_EN
WLAN_IRQ: U3.B7(PT22B_TDQ25) ; port WIFI_CONTROL.WLAN_IRQ
NetR52_1: R52.1 U9.3(OUT)

Not connected (* = marked no-connect by the designer): U3 A8(PT25A_TDQS25_P) A9(PT25B_TDQS25_N) A11(PT35A_TDQ34) A12(PT35B_TDQ34) A13(PT46A¦¦VREF1_1_TDQ43)* A14(PT46B¦¦VREF2_1_TDQ43) B9(PT28A¦¦PCLKT0_0_TDQ25) B10(PT28B¦¦PCLKC0_0_TDQ25) B11(PT31A¦¦PCLKT1_0_TDQ34)* B12(PT38A_TDQ43)* B13(PT43A_TDQS43_P) C2(PL6A) C9(PT26A_TDQ25) C10(PT26B_TDQ25) C11(PT31B¦¦PCLKC1_0_TDQ34) C12(PT38B_TDQ43)* C13(PT43B_TDQS43_N) D1(PL6B) D2(PL9B_LDQ14) E1(PL9A_LDQ14) E2(PL12A*_LDQ14) F1(PL14A_LDQS14_P) F3(PL12B*_LDQ14) G1(PL14B_LDQS14_N) G2(PL15A_LDQ14) G3(PL15B_LDQ14) H3(PL18A_LDQ23) H7(VTT7)* H14(VTT2)* J2(PL18B_LDQ23) K2(PL21A*¦¦LUM0_GDLLT_FB_A_LDQ23) K18(PR18A¦¦VREF1_2_RDQ23) L1(PL23B_LDQS23_N) L2(PL21B*¦¦LUM0_GDLLT_FB_B_LDQ23) L3(PL23A_LDQS23_P) L6(VTT6)* L14(VTT3)* L18(PR20A*¦¦RUM0_GDLLT_IN_A_RDQ23) L19(PR18B¦¦VREF2_2_RDQ23) M1(PL24B_LDQ23) M2(PL24A_LDQ23) M3(PL26A*¦¦PCLKT7_0_LDQ23) M7(VTT6)* M13(VTT3)* M17(PR20B*¦¦RUM0_GDLLT_IN_B_RDQ23) M18(PR26A*¦¦PCLKT2_0_RDQ23) M19(PR24B_RDQ23) N2(PL26E_C¦¦LUM0_GPLLT_IN_A)* N3(PL26B*¦¦PCLKC7_0_LDQ23) N17(PR26B*¦¦PCLKC2_0_RDQ23) N19(PR26E_D¦¦RUM0_GPLLT_IN_B)* P3(PL26E_D¦¦LUM0_GPLLT_IN_B)* P6(VTT6)* P19(PR29B*¦¦PCLKC3_0_RDQ32) U19(PR44B*_RDQ41) V18(PR53A*_RDQ50) V19(PR53B*_RDQ50)

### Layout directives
differential pair: RX_CLK_N, RX_CLK_P, RX_N, RX_P, TX_CLK_N, TX_CLK_P, TX_N, TX_P

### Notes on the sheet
- _A and _B are input only pads
- (near U3) 10uF Cap Shared for top side of FPGA
- VTT# Are termination voltages and unless we are using a specification that requires a termination these pins can be left floating
  Refere to page 275 of the ECP3 Handbook for more information
- ECP3 Handbook <http://d12lxohwf1zsq3.cloudfront.net/documents/HB1009.pdf>

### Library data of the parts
C3-C7 C26 C43 C45-C49 C51 C53 C54 C58 C62-C71 C73 = C_01005_0.1uF: as C41 on sheet Host Comm
C57 = C_0201_0.47µF: CAP CER 0.47UF 6.3V 20% JB 0201; Manufacturer: TDK Corporation; Manufacturer Part Number: C0603JB0J474M030BC
C59-C61 C72 = C_0402_10uF: CAP CER 10UF 4V 20% X5R 0402; Manufacturer: Taiyo Yuden; Manufacturer Part Number: AMK105CBJ106MV-F
R52 = R_01005_33: RES 33 OHM 1/32W 1% 01005; Manufacturer: Samsung Electro-Mechanics America, Inc; Manufacturer Part Number: RC0402F330CS; Temperature Coefficient: ±300ppm/°C
U3 = U_LFE3-17EA-MG328: IC FPGA 17KLUTS 116I/O 328-BGA; SPLIT_INST: TRUE; SWAP_INFO: (S1+S2+S3+S4+S5+S6+S7+S8+S9+S10); Number of LABs/CLBs: 2125; Number of Logic Elements/Cells: 17000; Total RAM Bits: 716800; Number of I /O: 116
U9 = U_ASA-19.200MHZ-L-T: OSC 19.200 MHZ 3.3V SMD; Function: Tri-State (Output Enable); Output: HCMOS, TTL; Frequency Stability: ±50ppm

## Sheet FPGA Serdes.SchDoc: FPGA SERDES
size B; Date: 10/29/2013; DrawnBy: David McCoy; Engineer: David McCoy (Cospan Design); DocumentNumber: 6; Revision: A; SheetNumber: 6; SheetTotal: 11
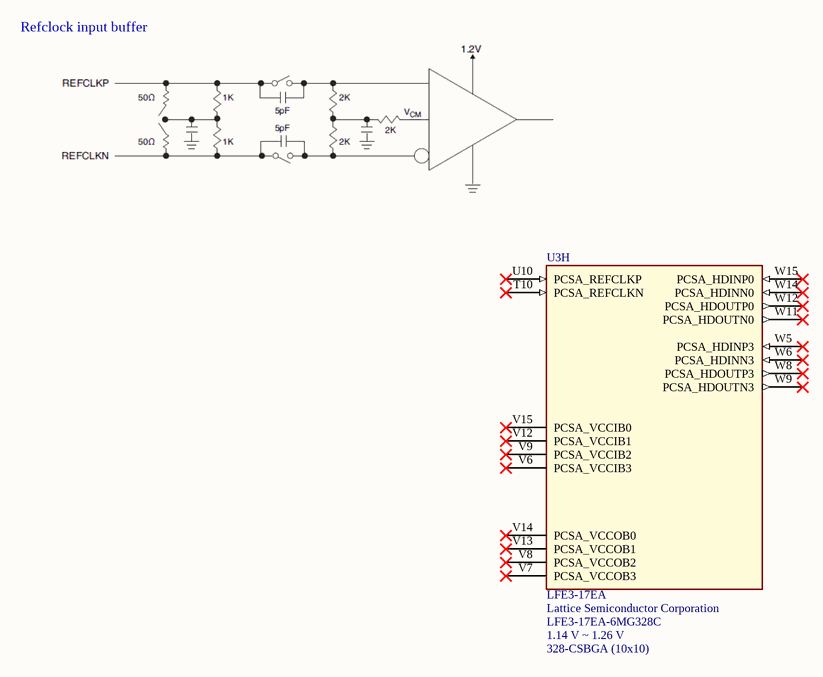
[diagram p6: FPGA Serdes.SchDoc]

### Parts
U3  LFE3-17EA  Manufacturer: Lattice Semiconductor Corporation  Manufacturer Part Number: LFE3-17EA-6MG328C  Voltage - Supply: 1.14 V ~ 1.26 V  Supplier Device Package: 328-CSBGA (10x10)  [BGA328C50P19X19_1000X1000X150]  (part H of 10)

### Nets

Not connected (* = marked no-connect by the designer): U3 T10(PCSA_REFCLKN)* U10(PCSA_REFCLKP)* V6(PCSA_VCCIB3)* V7(PCSA_VCCOB3)* V8(PCSA_VCCOB2)* V9(PCSA_VCCIB2)* V12(PCSA_VCCIB1)* V13(PCSA_VCCOB1)* V14(PCSA_VCCOB0)* V15(PCSA_VCCIB0)* W5(PCSA_HDINP3)* W6(PCSA_HDINN3)* W8(PCSA_HDOUTP3)* W9(PCSA_HDOUTN3)* W11(PCSA_HDOUTN0)* W12(PCSA_HDOUTP0)* W14(PCSA_HDINN0)* W15(PCSA_HDINP0)*

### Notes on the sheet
- Refclock input buffer

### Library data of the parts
U3 = U_LFE3-17EA-MG328: as U3 on sheet FPGA Banks

## Sheet FPGA Power.SchDoc: FPGA Power
size B; Date: 10/29/2013; DrawnBy: David McCoy; Engineer: David McCoy (Cospan Design); DocumentNumber: 7; Revision: A; SheetNumber: 7; SheetTotal: 11
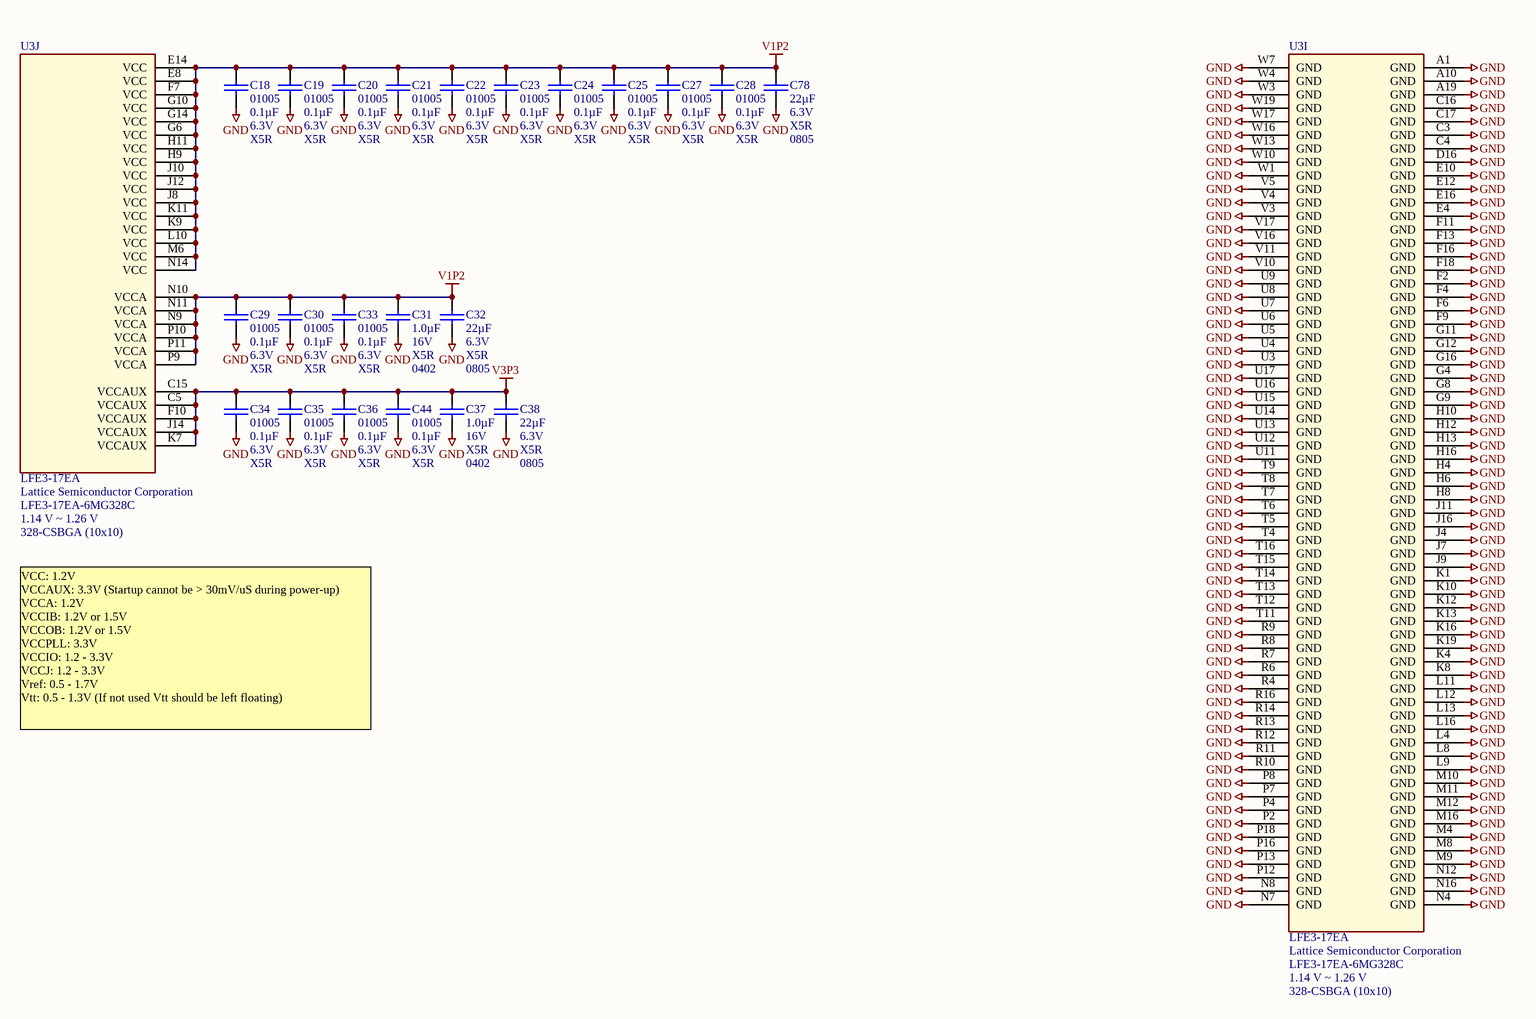
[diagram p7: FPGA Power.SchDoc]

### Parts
C18  Package / Case: 01005  Capacitance: 0.1µF  Voltage - Rated: 6.3V  Temperature Coefficient: X5R  [C_01005]  (hidden comment: 0.1uF)
C19  Package / Case: 01005  Capacitance: 0.1µF  Voltage - Rated: 6.3V  Temperature Coefficient: X5R  [C_01005]  (hidden comment: 0.1uF)
C20  Package / Case: 01005  Capacitance: 0.1µF  Voltage - Rated: 6.3V  Temperature Coefficient: X5R  [C_01005]  (hidden comment: 0.1uF)
C21  Package / Case: 01005  Capacitance: 0.1µF  Voltage - Rated: 6.3V  Temperature Coefficient: X5R  [C_01005]  (hidden comment: 0.1uF)
C22  Package / Case: 01005  Capacitance: 0.1µF  Voltage - Rated: 6.3V  Temperature Coefficient: X5R  [C_01005]  (hidden comment: 0.1uF)
C23  Package / Case: 01005  Capacitance: 0.1µF  Voltage - Rated: 6.3V  Temperature Coefficient: X5R  [C_01005]  (hidden comment: 0.1uF)
C24  Package / Case: 01005  Capacitance: 0.1µF  Voltage - Rated: 6.3V  Temperature Coefficient: X5R  [C_01005]  (hidden comment: 0.1uF)
C25  Package / Case: 01005  Capacitance: 0.1µF  Voltage - Rated: 6.3V  Temperature Coefficient: X5R  [C_01005]  (hidden comment: 0.1uF)
C27  Package / Case: 01005  Capacitance: 0.1µF  Voltage - Rated: 6.3V  Temperature Coefficient: X5R  [C_01005]  (hidden comment: 0.1uF)
C28  Package / Case: 01005  Capacitance: 0.1µF  Voltage - Rated: 6.3V  Temperature Coefficient: X5R  [C_01005]  (hidden comment: 0.1uF)
C29  Package / Case: 01005  Capacitance: 0.1µF  Voltage - Rated: 6.3V  Temperature Coefficient: X5R  [C_01005]  (hidden comment: 0.1uF)
C30  Package / Case: 01005  Capacitance: 0.1µF  Voltage - Rated: 6.3V  Temperature Coefficient: X5R  [C_01005]  (hidden comment: 0.1uF)
C31  Capacitance: 1.0µF  Voltage - Rated: 16V  Temperature Coefficient: X5R  Package / Case: 0402  [C_ERA-0402]  (hidden comment: 1.0uF)
C32  Capacitance: 22µF  Voltage - Rated: 6.3V  Temperature Coefficient: X5R  Package / Case: 0805  [C_ERA-0805]  (hidden comment: 22uF)
C33  Package / Case: 01005  Capacitance: 0.1µF  Voltage - Rated: 6.3V  Temperature Coefficient: X5R  [C_01005]  (hidden comment: 0.1uF)
C34  Package / Case: 01005  Capacitance: 0.1µF  Voltage - Rated: 6.3V  Temperature Coefficient: X5R  [C_01005]  (hidden comment: 0.1uF)
C35  Package / Case: 01005  Capacitance: 0.1µF  Voltage - Rated: 6.3V  Temperature Coefficient: X5R  [C_01005]  (hidden comment: 0.1uF)
C36  Package / Case: 01005  Capacitance: 0.1µF  Voltage - Rated: 6.3V  Temperature Coefficient: X5R  [C_01005]  (hidden comment: 0.1uF)
C37  Capacitance: 1.0µF  Voltage - Rated: 16V  Temperature Coefficient: X5R  Package / Case: 0402  [C_ERA-0402]  (hidden comment: 1.0uF)
C38  Capacitance: 22µF  Voltage - Rated: 6.3V  Temperature Coefficient: X5R  Package / Case: 0805  [C_ERA-0805]  (hidden comment: 22uF)
C44  Package / Case: 01005  Capacitance: 0.1µF  Voltage - Rated: 6.3V  Temperature Coefficient: X5R  [C_01005]  (hidden comment: 0.1uF)
C78  Capacitance: 22µF  Voltage - Rated: 6.3V  Temperature Coefficient: X5R  Package / Case: 0805  [C_ERA-0805]  (hidden comment: 22uF)
U3  LFE3-17EA  Manufacturer: Lattice Semiconductor Corporation  Manufacturer Part Number: LFE3-17EA-6MG328C  Voltage - Supply: 1.14 V ~ 1.26 V  Supplier Device Package: 328-CSBGA (10x10)  [BGA328C50P19X19_1000X1000X150]  (parts I,J of 10)

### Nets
GND: C18.1 C19.1 C20.1 C21.1 C22.1 C23.1 C24.1 C25.1 C27.1 C28.1 C29.1 C30.1 C31.1 C32.1 C33.1 C34.1 C35.1 C36.1 C37.1 C38.1 C44.1 C78.1 U3.A1(GND) U3.A10(GND) U3.A19(GND) U3.C3(GND) U3.C4(GND) U3.C16(GND) U3.C17(GND) U3.D16(GND) U3.E4(GND) U3.E10(GND) U3.E12(GND) U3.E16(GND) U3.F2(GND) U3.F4(GND) U3.F6(GND) U3.F9(GND) U3.F11(GND) U3.F13(GND) U3.F16(GND) U3.F18(GND) U3.G4(GND) U3.G8(GND) U3.G9(GND) U3.G11(GND) U3.G12(GND) U3.G16(GND) U3.H4(GND) U3.H6(GND) U3.H8(GND) U3.H10(GND) U3.H12(GND) U3.H13(GND) U3.H16(GND) U3.J4(GND) U3.J7(GND) U3.J9(GND) U3.J11(GND) U3.J16(GND) U3.K1(GND) U3.K4(GND) U3.K8(GND) U3.K10(GND) U3.K12(GND) U3.K13(GND) U3.K16(GND) U3.K19(GND) U3.L4(GND) U3.L8(GND) U3.L9(GND) U3.L11(GND) U3.L12(GND) U3.L13(GND) U3.L16(GND) U3.M4(GND) U3.M8(GND) U3.M9(GND) U3.M10(GND) U3.M11(GND) U3.M12(GND) U3.M16(GND) U3.N4(GND) U3.N7(GND) U3.N8(GND) U3.N12(GND) U3.N16(GND) U3.P2(GND) U3.P4(GND) U3.P7(GND) U3.P8(GND) U3.P12(GND) U3.P13(GND) U3.P16(GND) U3.P18(GND) U3.R4(GND) U3.R6(GND) U3.R7(GND) U3.R8(GND) U3.R9(GND) U3.R10(GND) U3.R11(GND) U3.R12(GND) U3.R13(GND) U3.R14(GND) U3.R16(GND) U3.T4(GND) U3.T5(GND) U3.T6(GND) U3.T7(GND) U3.T8(GND) U3.T9(GND) U3.T11(GND) U3.T12(GND) U3.T13(GND) U3.T14(GND) U3.T15(GND) U3.T16(GND) U3.U3(GND) U3.U4(GND) U3.U5(GND) U3.U6(GND) U3.U7(GND) U3.U8(GND) U3.U9(GND) U3.U11(GND) U3.U12(GND) U3.U13(GND) U3.U14(GND) U3.U15(GND) U3.U16(GND) U3.U17(GND) U3.V3(GND) U3.V4(GND) U3.V5(GND) U3.V10(GND) U3.V11(GND) U3.V16(GND) U3.V17(GND) U3.W1(GND) U3.W3(GND) U3.W4(GND) U3.W7(GND) U3.W10(GND) U3.W13(GND) U3.W16(GND) U3.W17(GND) U3.W19(GND)
V1P2: C18.2 C19.2 C20.2 C21.2 C22.2 C23.2 C24.2 C25.2 C27.2 C28.2 C29.2 C30.2 C31.2 C32.2 C33.2 C78.2 U3.E8(VCC) U3.E14(VCC) U3.F7(VCC) U3.G6(VCC) U3.G10(VCC) U3.G14(VCC) U3.H9(VCC) U3.H11(VCC) U3.J8(VCC) U3.J10(VCC) U3.J12(VCC) U3.K9(VCC) U3.K11(VCC) U3.L10(VCC) U3.M6(VCC) U3.N9(VCCA) U3.N10(VCCA) U3.N11(VCCA) U3.N14(VCC) U3.P9(VCCA) U3.P10(VCCA) U3.P11(VCCA)
V3P3: C34.2 C35.2 C36.2 C37.2 C38.2 C44.2 U3.C5(VCCAUX) U3.C15(VCCAUX) U3.F10(VCCAUX) U3.J14(VCCAUX) U3.K7(VCCAUX)

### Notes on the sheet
- VCC: 1.2V
  VCCAUX: 3.3V (Startup cannot be > 30mV/uS during power-up)
  VCCA: 1.2V
  VCCIB: 1.2V or 1.5V
  VCCOB: 1.2V or 1.5V
  VCCPLL: 3.3V
  VCCIO: 1.2 - 3.3V
  VCCJ: 1.2 - 3.3V
  Vref: 0.5 - 1.7V
  Vtt: 0.5 - 1.3V (If not used Vtt should be left floating)

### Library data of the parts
C18-C25 C27-C30 C33-C36 C44 = C_01005_0.1uF: as C41 on sheet Host Comm
C31 C37 = C_0402_1.0UF_16V: CAP CER 1.0UF 16V X5R 0402; Manufacturer: TDK Corporation; Manufacturer Part Number: C1005X5R1C105K; Tolerance: ±10%
C32 C38 C78 = C_0805_22UF_6.3V: CAP CER 22UF 6.3V X7R 10% 0805; Manufacturer: AVX Corporation; Manufacturer Part Number: 08056D226MAT2A; Tolerance: ±20%
U3 = U_LFE3-17EA-MG328: as U3 on sheet FPGA Banks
